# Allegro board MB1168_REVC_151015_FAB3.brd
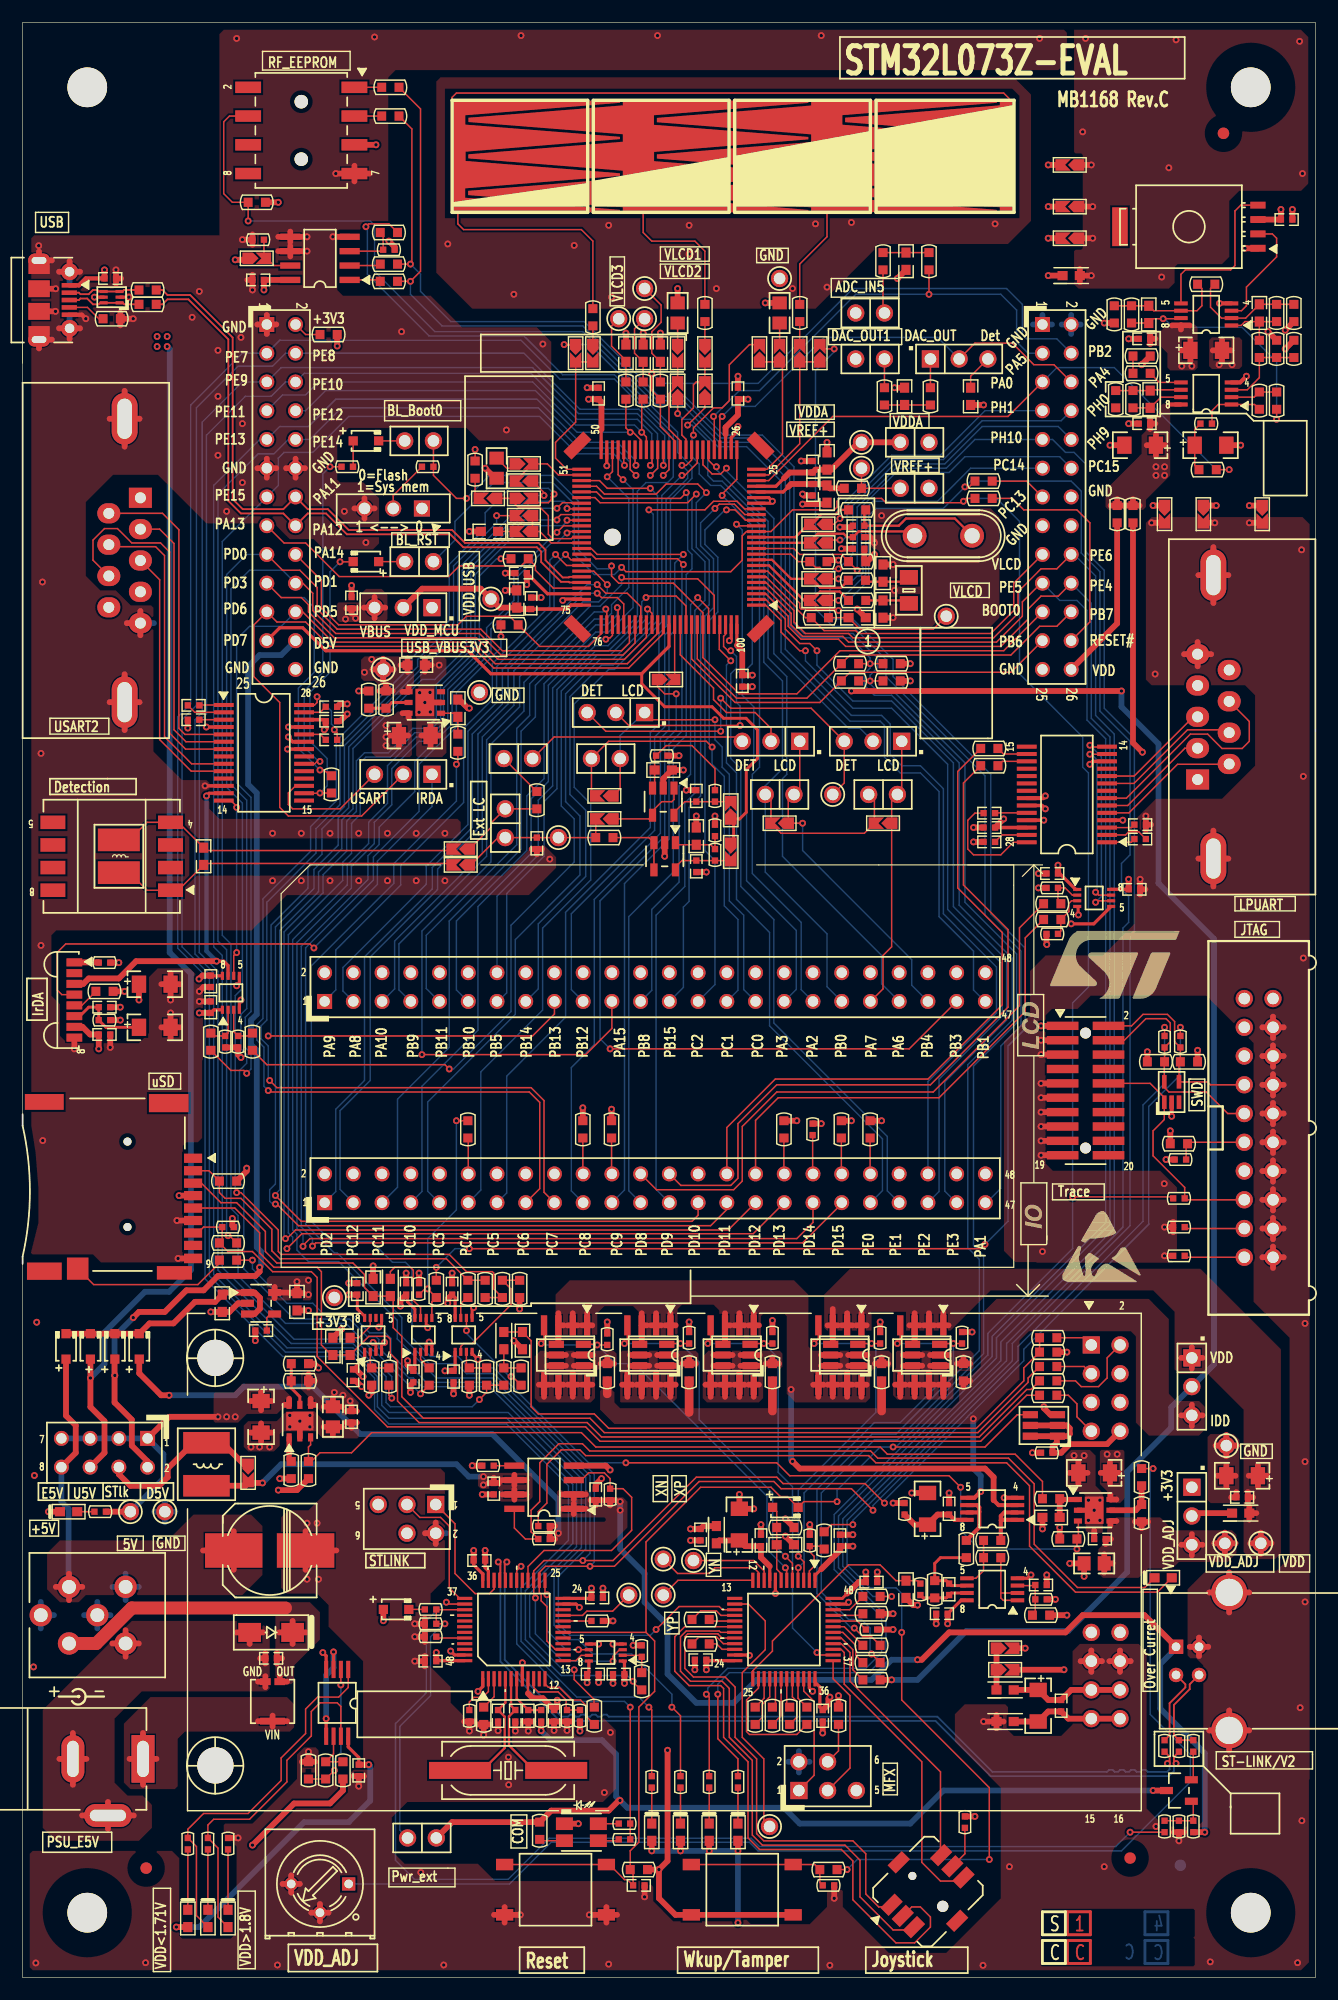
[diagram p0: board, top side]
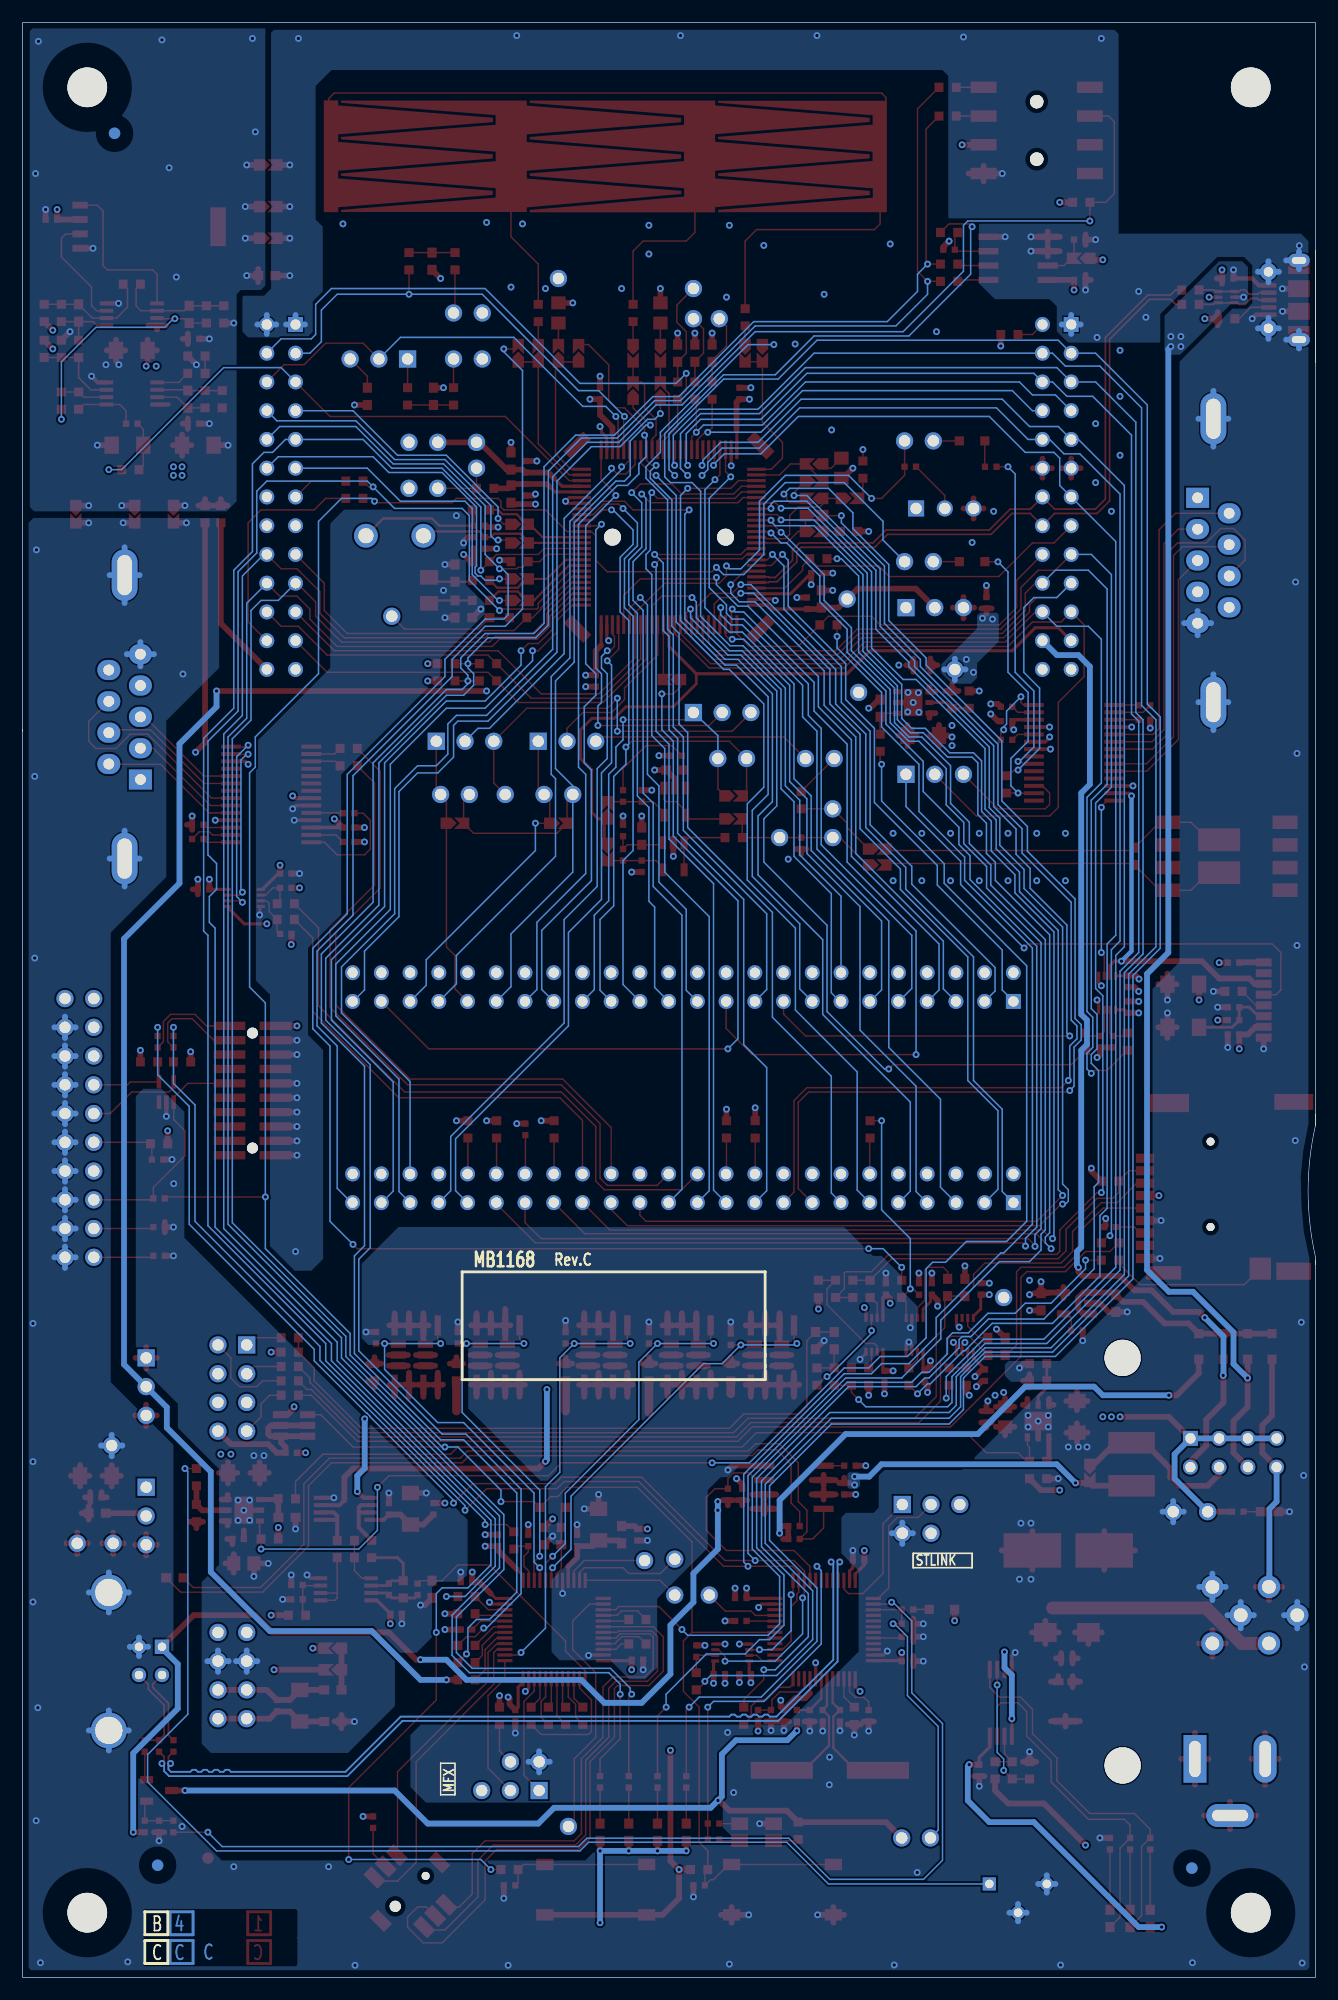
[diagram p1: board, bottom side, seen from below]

Outline 114.3 x 172.72 mm; copper layers: TOP, L2_VCC, L3_GND, BOTTOM. Coordinates in mm from the lower left corner of the outline.
Outline path: 0,76.26 0,76.2 0,172.72 114.3,172.72 114.3,110.11 114.3,110.29 114.3,0 0,0 0,63.37 0,63.01 0,63.69 arc(0.64,69.47) 0,75.25 ; 0,76.26 0,75.25 ; 0,76.26 0,75.25

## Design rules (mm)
net group DIFFPAIR2: nets PA11 PA12
net group DIFFPAIR3: nets STL_USB_DM STL_USB_DP
net group MICROB: nets MICROB_N MICROB_P

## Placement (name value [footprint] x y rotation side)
B1  RESET  [PB10]  47.12 7.75 0 top
B2  WKUP  [PB10]  63.63 7.75 0 top
B3  MT008-A  [MT-008A]  80.01 7.62 315 top
C1  100nF  [0402C]  111.76 155.32 180 top
C2  [N_A]  [0603C]  78.11 151.64 90 top
C3  100nF  [0402C]  20.83 149.99 0 top
C4  47nF  [0805C]  57.91 147.07 270 top
C5  47nF  [0805C]  66.93 147.07 270 top
C6  1uF  [0603C]  109.35 147.07 270 top
C7  1uF  [0603C]  99.57 146.94 270 top
C8  100nF  [0402C]  99.19 144.78 0 top
C9  1uF  [TAN-A]  104.65 143.76 180 top
C10  1uF  [0603C]  53.34 143.51 270 top
C11  1uF  [0603C]  54.86 143.51 270 top
C12  1uF  [0603C]  56.39 143.51 270 top
C13  100nF  [0402C]  50.93 139.95 270 top
C14  100nF  [0402C]  63.25 139.95 270 top
C15  [N_A]  [0603C]  77.98 139.7 270 top
C16  [N_A]  [0603C]  99.69 139.45 90 top
C17  100nF  [0402C]  99.19 137.29 0 top
C18  1uF  [TAN-A]  98.81 135.38 0 top
C19  10uF  [TAN-A]  105.03 135.38 180 top
C20  1uF  [0603C]  71.12 133.99 90 top
C21  100nF  [0402C]  69.85 133.48 270 top
C22  47nF  [0805C]  41.91 133.35 90 top
C23  100nF  [0402C]  69.85 131.44 90 top
C24  1uF  [0603C]  71.12 131.06 270 top
C25  20pF  [0402C]  73.91 128.27 180 top
C26  220nF  [0603C]  41.27 127.76 0 top
C27  20pF  [0402C]  73.91 127.25 0 top
C28  100nF  [0402C]  73.91 126.24 0 top
C29  100nF  [0402C]  44.07 124.08 0 top
C30  2.7pF  [0603C]  76.07 124.08 90 top
C31  1uF  [0603C]  43.69 121.79 90 top
C32  100nF  [0402C]  29.08 121.46 90 top
C33  100nF  [0402C]  44.96 121.41 270 top
C34  2.7pF  [0603C]  76.07 120.9 270 top
C35  1uF  [0603C]  73.79 120.14 180 top
C36  1uF  [0603C]  34.8 115.95 0 top
C37  100nF  [0402C]  63.63 114.55 90 top
C38  100nF  [0402C]  15.11 112.39 180 top
C39  100nF  [0402C]  27.3 112.27 0 top
C40  1nF  [0603C]  16 99.06 90 top
C41  1nF  [0603C]  38.48 112.14 90 top
C42  100nF  [0402C]  15.11 111.12 180 top
C43  100nF  [0402C]  27.3 111 180 top
C44  4.7uF  [TAN-A]  34.67 109.73 180 top
C45  100nF  [0402C]  27.3 109.35 0 top
C46  100pF  [0402C]  45.47 100.2 90 top
C47  [N_A]  [0603C]  56.64 106.68 0 top
C48  100nF  [0402C]  50.67 42.67 90 top
C49  100nF  [0402C]  7.75 150.11 0 top
C50  100nF  [0402C]  85.47 102.87 180 top
C51  100nF  [0402C]  98.81 101.85 0 top
C52  100nF  [0402C]  85.47 101.6 0 top
C53  100nF  [0402C]  98.81 100.58 0 top
C54  100nF  [0402C]  41.66 43.18 90 top
C55  100nF  [0402C]  85.47 100.33 180 top
C56  100nF  [0402C]  91.03 97.54 0 top
C57  [N_A]  [0603C]  59.56 100.84 90 top
C58  100nF  [0402C]  59.56 104.39 90 top
C59  1nF  [0603C]  83.82 139.7 270 top
C60  100nF  [0402C]  98.3 96.14 180 top
C61  N_A  [0603C]  27.43 55.75 270 top
C62  N_A  [0603C]  30.99 60.96 270 top
C63  1nF  [0402C]  59.56 98.17 270 top
C64  100nF  [0402C]  16.64 88.01 90 top
C65  4.7uF  [TAN-A]  11.68 87.76 180 top
C66  100nF  [0402C]  7.24 85.72 180 top
C67  100nF  [0402C]  16.64 85.72 270 top
C68  4.7uF  [TAN-A]  11.68 83.95 180 top
C69  100nF  [0402C]  7.24 83.31 180 top
C70  100nF  [0402C]  29.59 60.83 270 top
C71  100nF  [0402C]  33.91 60.83 270 top
C72  100nF  [0402C]  37.97 60.83 270 top
C73  1uF  [0603C]  24.26 59.69 270 top
C74  1uF  [0603C]  17.65 59.56 270 top
C75  10nF  [0402C]  21.08 57.15 180 top
C76  100nF  [0402C]  29.21 53.21 90 top
C77  100nF  [0402C]  34.54 53.09 90 top
C78  100nF  [0402C]  38.1 53.09 90 top
C79  4.7uF  [TAN-A]  21.08 49.53 90 top
C80  10uF[ESR<0.2ohm]  [0805C]  27.43 49.53 270 top
C81  100nF  [0402C]  29.08 49.53 270 top
C82  4.7uF  [TAN-A]  94.74 44.58 0 top
C83  1uF  [TAN-A]  107.82 44.32 0 top
C84  N_A  [0603C]  44.2 56.26 90 top
C86  100nF  [0402C]  107.82 42.42 0 top
C87  10uF  [TAN-A]  80.01 41.4 270 top
C88  100nF  [0402C]  81.92 41.4 90 top
C89  [N_A]  [0603C]  90.93 40.64 0 top
C90  1uF  [TAN-A]  63.37 40.01 270 top
C91  100nF  [0402C]  59.94 39.12 90 top
C92  100nF  [0402C]  95.25 38.73 180 top
C93  100nF  [0402C]  65.28 38.61 270 top
C94  100nF  [0402C]  72.26 38.61 270 top
C95  [N_A]  [0603C]  67.44 38.23 180 top
C96  220uF  [C310M-6]  21.84 37.72 180 top
C97  100nF  [0402C]  40.39 36.83 180 top
C98  10uF[ESR<0.2ohm]  [0805C]  94.74 36.58 180 top
C99  100nF  [0402C]  75.06 34.92 180 top
C100  100nF  [0402C]  90.04 34.67 0 top
C101  1uF  [0603C]  78.11 34.29 90 top
C102  100nF  [0402C]  81.92 34.29 270 top
C103  100nF  [0402C]  50.8 33.53 180 top
C104  100nF  [0402C]  81.28 32.13 180 top
C105  100nF  [0402C]  21.97 28.19 180 top
C106  100nF  [0402C]  59.94 28.07 0 top
C107  100nF  [0402C]  36.07 27.94 0 top
C108  100nF  [0402C]  50.42 26.8 0 top
C109  100nF  [0402C]  52.7 26.8 180 top
C110  10uF  [TAN-A]  89.79 24 90 top
C111  100nF  [0402C]  91.82 24 270 top
C112  20pF  [0402C]  42.04 23.11 90 top
C113  20pF  [0402C]  43.56 23.11 90 top
C114  100nF  [0402C]  44.7 23.11 90 top
C115  100nF  [0402C]  46.99 23.11 270 top
C116  100nF  [0402C]  70.74 23.11 270 top
C117  100nF  [0402C]  29.72 18.29 90 top
C118  100nF  [0402C]  54.48 8.13 180 top
CN1  -  [SSM-104-L-DH]  24.64 163.19 90 top
CN2  Header 2X1  [SIP2]  73.66 147.07 0 top
CN3  Header 2X1  [SIP2]  73.66 143 0 top
CN4  Header 13X2  [HDR_2X13_2R54]  21.59 146.05 270 top
CN5  Header 13X2  [HDR_2X13_2R54]  90.17 146.05 270 top
CN6  DB9-male  [DB9_M]  10.41 125.2 90 top
CN7  DB9-male  [DB9_M]  103.89 111.38 270 top
CN8  Header 2X1  [SIP2]  42.67 100.71 90 top
CN9  1050170001  [MICRO_USB_B_105017]  4.05 148.21 270 top
CN10  Header 24X2  [HDR_2X24_2R54]  26.7 86.23 0 top
CN11  -  [FTSH-110-01-L-DV]  93.98 78.36 270 top
CN12  JTAG  [IDC20S]  108.01 86.49 0 top
CN13  PJS008-2000 (SMS064FF or SMS128FF)  [MSD_PJS008_]  9.27 73.85 270 top
CN14  Header 24X2  [HDR_2X24_2R54]  26.7 68.45 0 top
CN15  [N_A]  [HDR_2X3-1_2R54-6]  36.52 41.78 180 top
CN16  2.4" LCD connector (MB895_S)  [MB895CS]  94.49 55.88 0 top
CN17  USB-typeB connector  [USB-B]  101.98 29.21 90 top
CN18  DC-10B  [PWR_JACK_DC10]  10.64 19.3 0 top
CN19  [N_A]  [HDR_2X3-1_2R54-6]  68.63 16.51 0 top
D1  BAT60JFILM  [SOD-323]  30.35 135.76 0 top
D2  BAT60JFILM  [SOD-323]  30.35 125.09 180 top
D3  BAT60JFILM  [SOD-323]  3.84 55.75 90 top
D4  BAT60JFILM  [SOD-323]  5.99 55.75 90 top
D5  BAT60JFILM  [SOD-323]  8.15 55.75 90 top
D6  BAT60JFILM  [SOD-323]  10.31 55.75 90 top
D7  BAT60JFILM  [SOD-323]  33.02 32.51 0 top
D8  BAT60JFILM  [SOD-323]  67.44 41.53 0 top
JP1  -  [SIP3]  77.72 109.22 180 top
JP2  -  [SIP3]  80.26 143 0 top
JP3  -  [SIP2]  36.32 135.76 180 top
JP4  -  [SIP2]  80.14 135.64 180 top
JP5  -  [SIP2]  80.14 131.57 180 top
JP6  -  [SIP2]  36.32 125.09 180 top
JP7  -  [SIP3]  36.2 121.03 180 top
JP8  -  [SIP2]  42.55 107.7 0 top
JP9  -  [SIP3]  36.2 106.3 180 top
JP10  -  [SIP3]  103.38 54.74 270 top
JP11  Header 4X2  [HDR_2X4_2R54]  11.05 47.62 180 top
JP12  -  [SIP3]  103.38 43.31 270 top
JP13  -  [SIP2]  36.58 12.32 180 top
JP14  -  [SIP2]  74.8 104.52 0 top
JP15  -  [SIP3]  68.71 109.22 180 top
JP16  -  [SIP2]  65.66 104.52 0 top
JP17  -  [SIP3]  54.99 111.76 180 top
JP18  -  [SIP2]  50.29 107.7 0 top
L1  BEAD  [0603L]  92.71 150.37 0 top
L2  100uH  [ER95]  7.87 99.06 180 top
L3  [N_A)  [LSM2_4R4X3R2_H3]  8.51 99.06 90 top
L4  BEAD  [0603L]  28.96 55.75 270 top
L5  82 10%  [LSM2_4R9X4R9_H4R1]  16.26 45.34 270 top
L6  BEAD  [0603L]  107.7 41.02 0 top
L7  BEAD  [0603L]  61.34 39.12 270 top
L8  BNX002-01  [BNX001]  6.6 32 180 top
L9  BEAD  [0603L]  86.87 25.4 0 top
L10  BEAD  [0603L]  86.87 22.61 0 top
L11  BEAD  [0603L]  32.51 60.96 270 top
L12  BEAD  [0603L]  42.55 56.26 90 top
LD1  Green  [0603D]  63.25 12.83 90 top
LD2  Orange  [0603D]  60.71 12.83 90 top
LD3  Red  [0603D]  58.17 12.83 90 top
LD4  Blue  [0603D]  55.63 12.83 90 top
LD5  Red  [0603D]  4.06 41.15 180 top
LD6  HSMF-A201-A00J1  [LED2_3528]  49.4 12.83 270 top
LD7  Red  [0603D]  14.61 5.21 90 top
LD8  Orange  [0603D]  16.38 5.21 90 top
LD9  Green  [0603D]  18.16 5.21 90 top
LD10  Red  [0603D]  100.84 35.31 180 top
LS1  LS4  [LINEAR_SENSOR3_ELECTRODES]  37.97 155.96 0 top
NOREF  -  []  395.73 -43.74 0 top
NOREF#2  -  [unnamed#2]  5.71 167 0 top
NOREF#3  -  []  93.39 1.48 0 top
NOREF#4  -  []  0 0 0 top
NOREF#5  -  [unnamed#2]  108.58 5.71 0 top
NOREF#6  -  [unnamed#2]  108.58 167 0 top
NOREF#7  -  [unnamed#2]  10.92 9.65 0 top
NOREF#8  -  []  -0.51 -7.11 0 top
NOREF#9  -  []  0 172.72 0 top
NOREF#10  -  [unnamed#2]  106.17 162.94 0 top
NOREF#11  -  []  93.39 4.02 0 top
NOREF#12  -  [unnamed#2]  5.71 5.71 0 top
NOREF#13  -  []  233.48 163.12 0 top
NOREF#14  -  []  170.18 202.69 0 top
NOREF#15  -  [unnamed#2]  97.92 10.54 0 top
NOREF#16  -  []  114.3 0 90 top
NOREF#17  -  []  6.35 209.55 0 top
NOREF#18  -  [unnamed#2]  10.92 9.65 180 bottom
NOREF#19  -  [unnamed#2]  106.17 162.94 180 bottom
NOREF#20  -  [unnamed#2]  102.36 9.91 180 bottom
R1  0  [0603R]  32.51 167 180 top
R2  0  [0603R]  32.51 164.47 180 top
R3  [N_A]  [0603R]  20.7 156.84 0 top
R4  0  [0603R]  32.38 154.18 0 top
R5  10K  [0402R]  20.83 153.54 180 top
R6  10K  [0402R]  32.38 152.65 180 top
R7  0  [0603R]  76.07 151.64 90 top
R8  0  [0603R]  80.14 151.64 270 top
R9  0  [0603R]  32.38 151.38 180 top
R10  0  [0603R]  32.38 149.86 180 top
R11  220 0.1%  [0603R]  104.65 149.61 180 top
R12  10K  [0603R]  60.33 147.07 90 top
R13  10K  [0603R]  68.71 147.07 90 top
R14  47K 0.1%  [0603R]  110.87 147.07 90 top
R15  27400 0.1%  [0603R]  112.39 147.07 90 top
R16  27400 0.1%  [0603R]  96.52 146.94 270 top
R17  47K 0.1%  [0603R]  98.04 146.94 90 top
R18  10K  [0603R]  50.42 146.69 90 top
R19  0  [0603R]  27.05 145.16 180 top
R20  10K 0.1%  [0603R]  109.35 143.89 90 top
R21  20K 0.1%  [0603R]  110.87 143.89 90 top
R22  20K 0.1%  [0603R]  112.39 143.89 90 top
R23  0  [0603R]  98.93 143.26 0 top
R24  0  [0603R]  98.93 141.73 180 top
R25  0  [0603R]  53.34 140.21 90 top
R26  0  [0603R]  54.86 140.21 90 top
R27  0  [0603R]  56.39 140.21 90 top
R28  0  [0603R]  76.2 139.7 270 top
R29  0  [0603R]  80.26 139.7 90 top
R30  [N_A]  [0603R]  96.65 139.45 270 top
R31  0  [0603R]  98.17 139.45 90 top
R32  10K 0.1%  [0603R]  109.35 139.32 90 top
R33  10K 0.1%  [0603R]  110.87 139.32 270 top
R34  100  [0402R]  104.65 137.29 0 top
R35  150  [0402R]  28.7 133.48 180 top
R36  10K  [0402R]  35.81 133.48 180 top
R37  10K  [0603R]  40.01 133.22 270 top
R38  0  [0603R]  104.78 133.22 0 top
R39  820  [0603R]  84.96 132.21 0 top
R40  0  [0603R]  73.41 131.57 180 top
R41  820  [0603R]  84.96 130.68 0 top
R42  390  [0603R]  73.79 129.67 0 top
R43  [N_A]  [0603R]  96.77 129.29 90 top
R44  0  [0603R]  98.17 129.29 90 top
R45  0  [0603R]  43.94 125.35 0 top
R46  [N_A]  [0603R]  70.36 125.09 180 top
R47  [N_A]  [0603R]  73.79 125.09 180 top
R48  0  [0603R]  73.76 123.44 180 top
R49  0  [0603R]  73.79 121.67 180 top
R50  0  [0603R]  70.48 120.14 0 top
R51  0  [0603R]  43.05 119.51 0 top
R52  0  [0603R]  73.15 116.08 0 top
R53  1K2  [0603R]  76.83 116.08 0 top
R54  330K  [0402R]  61.21 104.39 90 top
R55  0  [0603R]  73.15 114.55 0 top
R56  1K2  [0603R]  76.83 114.55 0 top
R57  11.8K[1%]  [0603R]  30.61 112.9 90 top
R58  20.5K[1%]  [0603R]  32.13 112.9 270 top
R59  120  [0603R]  45.47 104.01 90 top
R60  820  [0603R]  38.48 109.09 90 top
R61  0  [0603R]  85.47 108.58 0 top
R62  0  [0603R]  85.47 107.06 0 top
R63  0  [0603R]  27.3 105.41 90 top
R64  330K  [0402R]  56.52 107.95 0 top
R65  1K  [0402R]  46.1 39.88 180 top
R66  2K2  [0402R]  41.15 45.21 180 top
R67  0  [0603R]  51.44 100.71 0 top
R68  100K  [0402R]  46.1 38.73 180 top
R69  0  [0603R]  11.05 149.1 180 top
R70  0  [0603R]  11.05 147.83 180 top
R71  10K  [0402R]  51.94 42.67 270 top
R72  0  [0603R]  90.68 56.52 0 top
R73  330K  [0402R]  61.21 99.19 90 top
R74  100K  [0603R]  7.87 146.56 180 top
R75  0  [0603R]  90.68 52.7 0 top
R76  330K  [0402R]  61.21 101.35 90 top
R83  100K  [0402R]  91.03 96.27 180 top
R87  0  [0603R]  91.03 94.87 0 top
R88  0  [0603R]  91.03 93.47 0 top
R89  100K  [0402R]  91.03 92.2 180 top
R90  5.1  [0402R]  7.24 89.66 180 top
R91  0  [0603R]  7.24 87.12 0 top
R92  47  [0402R]  7.24 84.58 180 top
R93  0  [0603R]  16.64 82.68 270 top
R94  100K  [0402R]  17.91 82.68 270 top
R95  100K  [0402R]  19.05 82.68 270 top
R96  0  [0603R]  20.32 82.68 270 top
R97  22  [0402R]  100.97 82.68 90 top
R98  22  [0402R]  102.36 82.68 90 top
R99  [N_A]  [0603R]  100.2 80.9 0 top
R100  [N_A]  [0603R]  103.12 80.9 0 top
R101  [N_A]  [0603R]  39.37 74.93 270 top
R102  330  [0603R]  49.53 74.93 270 top
R103  330  [0603R]  52.07 74.93 270 top
R104  330  [0603R]  67.31 74.93 270 top
R105  1K  [0402R]  69.85 74.93 90 top
R106  10K  [0603R]  72.39 74.93 270 top
R107  100K  [0603R]  74.93 74.93 270 top
R108  [N_A]  [0603R]  102.23 73.66 180 top
R109  10K  [0402R]  102.36 72.26 0 top
R110  [N_A]  [0603R]  18.16 70.36 0 top
R111  22  [0402R]  102.23 68.83 180 top
R112  10K  [0402R]  18.16 66.29 180 top
R113  10K  [0402R]  102.23 66.29 0 top
R114  0  [0603R]  18.16 64.9 0 top
R115  10K  [0402R]  102.23 63.75 0 top
R116  0  [0603R]  18.16 63.37 180 top
R117  10K  [0402R]  35.05 60.83 90 top
R118  0  [0603R]  36.58 60.83 90 top
R119  0  [0603R]  39.37 60.83 270 top
R120  [N_A]  [0603R]  40.89 60.83 90 top
R121  0  [0603R]  42.42 60.83 270 top
R122  100K  [0603R]  43.94 60.83 270 top
R123  100K  [0402R]  58.93 56.52 90 top
R124  100K  [0402R]  66.29 56.52 90 top
R125  100K  [0402R]  75.82 56.52 90 top
R126  100K  [0402R]  83.06 56.52 90 top
R127  100K  [0402R]  51.69 56.39 90 top
R128  [N_A]  [0603R]  90.68 55.24 0 top
R129  11.8K[1%]  [0603R]  24.51 54.23 0 top
R130  100 [1%]  [0603R]  51.69 53.47 90 top
R131  10 [1%]  [0603R]  58.93 53.47 90 top
R132  1K [1%]  [0603R]  66.29 53.47 90 top
R133  10K [1%]  [0603R]  75.95 53.47 90 top
R134  1 [1%]  [0603R]  83.19 53.47 90 top
R135  270  [0603R]  90.68 53.98 180 top
R136  100K  [0603R]  30.86 53.09 270 top
R137  0  [0603R]  32.38 53.09 270 top
R138  0  [0603R]  35.94 53.09 270 top
R139  100K  [0603R]  39.5 53.09 270 top
R140  0  [0603R]  41.02 53.09 90 top
R141  [N_A]  [0603R]  42.55 53.09 90 top
R142  0  [0603R]  44.07 53.09 270 top
R143  20.5K[1%]  [0603R]  24.51 52.7 180 top
R144  270  [0603R]  90.68 51.44 0 top
R145  4K7  [0402R]  90.55 46.35 180 top
R147  [N_A]  [0603R]  23.75 44.83 270 top
R148  1M  [0603R]  25.27 44.83 90 top
R149  10.2K[1%]  [0603R]  98.93 44.2 90 top
R150  0  [0603R]  90.93 42.29 0 top
R151  100  [0402R]  77.98 41.4 270 top
R153  1K  [0402R]  6.86 41.15 0 top
R154  20K[1%]  [0603R]  98.93 41.02 90 top
R155  [N_A]  [0603R]  67.44 39.75 180 top
R156  1M  [0603R]  92.46 38.73 0 top
R157  100K  [0402R]  69.6 38.61 90 top
R158  0  [0603R]  70.87 38.61 270 top
R159  1K [0.1%]  [0603R]  85.72 38.61 180 top
R162  1K [0.1%]  [0603R]  83.44 37.85 270 top
R163  49K9 [0.1%]  [0603R]  85.72 37.08 0 top
R164  100  [0402R]  79.38 34.29 270 top
R165  49K9 [0.1%]  [0603R]  80.64 34.29 270 top
R166  0  [0603R]  75.06 33.66 180 top
R167  1K  [0402R]  90.04 33.4 0 top
R168  2K2  [0402R]  36.07 32.51 180 top
R169  10K  [0603R]  75.06 32.13 180 top
R170  22K  [0603R]  90.04 32 180 top
R171  10K  [0603R]  59.94 31.62 180 top
R172  100K  [0402R]  50.8 31.5 0 top
R173  4K7  [0402R]  36.07 31.24 0 top
R174  510  [0402R]  75.06 30.73 0 top
R175  100K  [0402R]  36.07 30.1 180 top
R176  [N_A]  [0603R]  59.94 29.46 0 top
R177  0  [0603R]  75.06 29.34 180 top
R178  100K  [0402R]  54.74 28.83 270 top
R179  0  [0603R]  75.06 27.81 180 top
R180  0  [0603R]  75.06 26.29 0 top
R181  0  [0603R]  54.74 26.16 90 top
R182  10K  [0402R]  39.5 23.11 90 top
R183  [N_A]  [0603R]  40.77 23.11 90 top
R184  100K  [0402R]  45.85 23.11 270 top
R185  4K7  [0402R]  48.13 23.11 270 top
R186  4K7  [0402R]  49.28 23.11 90 top
R187  0  [0603R]  50.55 23.11 90 top
R188  10K  [0603R]  64.77 23.11 90 top
R189  10K  [0603R]  66.29 23.11 90 top
R190  10K  [0603R]  67.82 23.11 90 top
R191  10K  [0603R]  69.34 23.11 90 top
R192  0  [0603R]  72.14 23.11 90 top
R193  22  [0402R]  100.97 20.45 90 top
R194  22  [0402R]  102.23 20.45 90 top
R195  1.5K  [0402R]  103.5 20.45 90 top
R196  1.15K [1%]  [0603R]  25.27 18.29 90 top
R197  49.9 [1%]  [0603R]  26.8 18.29 270 top
R198  1K [1%]  [0603R]  28.32 18.29 90 top
R199  680  [0402R]  55.63 17.27 270 top
R200  680  [0402R]  58.17 17.27 270 top
R201  680  [0402R]  60.71 17.27 270 top
R202  510  [0402R]  63.25 17.27 270 top
R203  100  [0402R]  83.31 13.72 270 top
R204  100  [0402R]  53.21 13.59 180 top
R205  100  [0402R]  100.97 13.34 90 top
R206  36K  [0402R]  102.23 13.34 270 top
R207  10K  [0402R]  103.5 13.34 90 top
R208  0  [0603R]  45.72 12.95 90 top
R209  100  [0402R]  53.21 12.19 180 top
R210  1K  [0402R]  14.61 11.81 90 top
R211  1K  [0402R]  16.38 11.81 90 top
R212  1K  [0402R]  18.16 11.81 90 top
R213  [N_A]  [0603R]  54.48 9.53 0 top
R214  330  [0603R]  71.25 9.53 0 top
R215  220K  [0402R]  71.25 8.13 0 top
RV1  3386P-503H[5%]  [3386P]  26.29 8.26 180 top
SB1  Closed by default  [SB_0603]  92.58 160.15 0 top
SB2  Closed by default  [SB_0603]  92.58 156.46 0 top
SB3  Closed by default  [SB_0603]  92.58 153.67 0 top
SB4  Closed by default  [SB_0603]  20.7 151.89 180 top
SB5  Closed by default  [SB_0603]  48.9 143.51 90 top
SB6  Open by default  [SB_0603]  50.42 143.51 90 top
SB7  Open by default  [SB_0603]  57.91 143.51 90 top
SB8  Open by default  [SB_0603]  60.33 143.51 90 top
SB9  Closed by default  [SB_0603]  65.15 143.51 270 top
SB10  Open by default  [SB_0603]  66.93 143.51 270 top
SB11  Open by default  [SB_0603]  68.7 143.51 270 top
SB12  Closed by default  [SB_0603]  70.48 143.51 270 top
SB13  Closed by default  [SB_0603]  57.91 140.21 270 top
SB14  Closed by default  [SB_0603]  60.33 140.21 270 top
SB15  Open by default  [SB_0603]  44.32 133.73 180 top
SB16  Closed by default  [SB_0603]  44.32 132.21 0 top
SB17  Open by default  [SB_0603]  41.15 130.68 0 top
SB18  Closed by default  [SB_0603]  44.32 130.68 180 top
SB19  Closed by default  [SB_0603]  100.97 129.29 90 top
SB20  Closed by default  [SB_0603]  104.39 129.29 90 top
SB21  Closed by default  [SB_0603]  109.6 129.28 90 top
SB22  Closed by default  [SB_0603]  44.32 129.16 0 top
SB23  Open by default  [SB_0603]  70.36 128.39 0 top
SB24  Open by default  [SB_0603]  44.32 127.76 0 top
SB25  Open by default  [SB_0603]  70.36 126.74 0 top
SB26  Open by default  [SB_0603]  70.36 123.57 0 top
SB27  Open by default  [SB_0603]  70.36 121.67 0 top
SB28  Open by default  [SB_0603]  76.07 101.98 0 top
SB29  Closed by default  [SB_0603]  38.73 99.69 0 top
SB30  Closed by default  [SB_0603]  38.73 98.3 0 top
SB31  Closed by default  [SB_0603]  62.61 99.44 90 top
SB32  Open by default  [SB_0603]  62.61 103.12 270 top
SB33  Open by default  [SB_0603]  51.44 102.36 0 top
SB34  Open by default  [SB_0603]  66.93 101.98 0 top
SB35  Closed by default  [SB_0603]  56.9 114.68 180 top
SB36  Open by default  [SB_0603]  51.44 104.39 0 top
SB38  Open by default  [SB_0603]  19.94 44.58 90 top
SB40  Closed by default  [SB_0603]  86.87 29.09 180 top
SB41  Open by default  [SB_0603]  86.87 27.18 180 top
SW1  09.03290.01  [SW1_3TH_2R54_10X2R5]  35.31 129.79 180 top
T1  STS9P2UH7  [SOIC8_1R27_4R9X6]  48.01 54.99 180 top
T2  STT7P2UH7  [SOT23-6L]  48.39 54.99 90 top
T3  STS9P2UH7  [SOIC8_1R27_4R9X6]  55.37 54.99 180 top
T4  STT7P2UH7  [SOT23-6L]  55.75 54.99 90 top
T5  STS9P2UH7  [SOIC8_1R27_4R9X6]  62.74 54.99 180 top
T6  STT7P2UH7  [SOT23-6L]  63.12 54.99 90 top
T7  STS9P2UH7  [SOIC8_1R27_4R9X6]  72.26 54.99 180 top
T8  STT7P2UH7  [SOT23-6L]  72.64 54.99 90 top
T9  STS9P2UH7  [SOIC8_1R27_4R9X6]  79.5 54.99 180 top
T10  STT7P2UH7  [SOT23-6L]  79.88 54.99 90 top
T11  STT5N2VH5  [SOT23-6L]  90.3 48.77 90 top
T14  9013-SOT23  [SOT-23]  102.23 16.51 90 top
TP1  -  [TP]  66.93 150.11 0 top
TP2  -  [TP]  54.99 149.22 180 top
TP3  -  [TP]  52.7 146.56 270 top
TP4  -  [TP]  54.99 146.56 270 top
TP5  -  [TP]  74.17 135.64 0 top
TP6  -  [TP]  74.17 133.35 0 top
TP7  -  [TP]  41.4 121.79 0 top
TP8  -  [TP]  81.66 120.27 0 top
TP9  -  [TP]  31.88 115.57 90 top
TP10  -  [TP]  40.39 113.54 270 top
TP14  -  [TP]  47.37 100.71 90 top
TP18  -  [TP]  71.63 104.52 0 top
TP20  -  [TP]  27.56 60.07 0 top
TP21  -  [TP]  106.43 46.99 0 top
TP22  -  [TP]  9.53 41.15 180 top
TP23  -  [TP]  12.57 41.15 180 top
TP24  -  [TP]  106.3 38.35 90 top
TP25  -  [TP]  109.47 38.35 180 top
TP26  [N_A]  [TP]  56.64 36.96 90 top
TP27  [N_A]  [TP]  59.31 36.83 90 top
TP28  [N_A]  [TP]  53.59 33.78 0 top
TP29  [N_A]  [TP]  56.64 33.78 90 top
TP31  [N_A]  [TP]  66.04 13.34 0 top
U1  MPXM2102AS  [SENSOR_MPXM2102AS]  103.12 154.69 90 top
U2  STLM75M2F  [SOIC8_1R27_4R9X6]  26.29 151.89 90 top
U3  TSZ122IST  [MSOP8_0R65_3X4R9]  104.65 146.94 90 top
U4  TSZ122IST  [MSOP8_0R65_3X4R9]  104.65 139.95 90 top
U5  STM32L073VZT6  [IC149_100_025_B5]  57.15 127.25 90 top
U6  ST1L05BPUR  [DFN6_0R95_3X3]  35.56 112.65 90 top
U7  ST3241EBPR  [SSOP28_0R65_10R2X7R8]  21.34 108.2 270 top
U8  ST3241EBPR  [SSOP28_0R65_10R2X7R8]  92.33 104.52 90 top
U9  TSV631ILT  [SOT-23-5L]  56.77 99.06 180 top
U10  USBLC6-2P6 (optional)  [SOT-563]  7.87 148.46 90 top
U11  TSV911ILT  [SOT-23-5L]  56.64 103.89 180 top
U12  SN74LVC2T45DCUT  [USOP8_0R5_2X3R1]  94.74 95.38 270 top
U13  SN74LVC2T45DCUT  [USOP8_0R5_2X3R1]  18.41 87 0 top
U14  TFDU6300  [IR_VISHAY3]  4.57 86.36 90 top
U15  ESDALC6V1W5  [SOT-353]  101.59 78.23 0 top
U16  LD3985M33R  [SOT23-5]  21.08 59.56 270 top
U17  SN74LVC2T45DCUT  [USOP8_0R5_2X3R1]  30.99 56.77 0 top
U18  SN74LVC2T45DCUT  [USOP8_0R5_2X3R1]  35.43 56.77 0 top
U19  SN74LVC2T45DCUT  [USOP8_0R5_2X3R1]  38.99 56.77 0 top
U20  ST1L05BPUR  [DFN6_0R95_3X3]  24.51 49.15 0 top
U21  TSZ122IST  [MSOP8_0R65_3X4R9]  85.72 41.4 90 top
U22  ST1L05BPUR  [DFN6_0R95_3X3]  94.74 41.27 270 top
U23  TSZ122IST  [MSOP8_0R65_3X4R9]  85.72 34.29 90 top
U24  STLINK  [LQFP48_0R5_9X9]  43.43 30.73 90 top
U25  STM32L152CCT6  [LQFP48_0R5_9X9]  67.31 30.73 270 top
U26  SN74LVC2T45DCUT  [USOP8_0R5_2X3R1]  51.56 28.7 90 top
U27  ZEN056V130A24LS  [TYCO_ZEN056V130A24LS]  22.1 24.38 90 top
U28  TS3702IPT  [TSSOP8_0R65_3X6R4]  27.81 24.26 180 top
U29  ST890CDR  [SOIC8_1R27_4R9X6]  46.1 43.31 90 top
X1  8MHz (with socket)  [XTAL_SOCKET]  83.95 127.38 0 top
X2  NDK NX3215SA-32.768KHZ-EXS00A-MU00525  [XTAL_2SM_3R2X1R5]  78.36 122.56 270 top
X3  8MHz  [XTAL_2SM_12R7X4R7]  42.93 18.29 180 top
Z1  SMAJ5.0A-TR  [SMA]  21.97 30.48 0 top

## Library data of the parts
B1 B2 = PB10
B3 = MT-008A
C1 C3 C8 C13 C14 C17 C21 C23 C25 C27-C29 C32 C33 C37-C39 C42 C43 C45 C46 C48-C56 C58 C60 C63 C64 C66 C67 C69-C72 C75-C78 C81 C86 C88 C91-C94 C97 C99 C100 C102-C109 C111-C118 = 0402C
C2 C6 C7 C10-C12 C15 C16 C20 C24 C26 C30 C31 C34-C36 C40 C41 C47 C57 C59 C61 C62 C73 C74 C84 C89 C95 C101 = 0603C
C4 C5 C22 C80 C98 = 0805C
C9 C18 C19 C44 C65 C68 C79 C82 C83 C87 C90 C110 = TAN-A
C96 = C310M-6
CN1 = SSM-104-L-DH
CN2 CN3 CN8 JP3-JP6 JP8 JP13 JP14 JP16 JP18 = SIP2
CN4 CN5 = HDR_2X13_2R54
CN6 CN7 = DB9_M
CN9 = MICRO_USB_B_105017
CN10 CN14 = HDR_2X24_2R54
CN11 = FTSH-110-01-L-DV
CN12 = IDC20S
CN13 = MSD_PJS008_
CN15 CN19 = HDR_2X3-1_2R54-6
CN16 = MB895CS
CN17 = USB-B
CN18 = PWR_JACK_DC10
D1-D8 = SOD-323
JP1 JP2 JP7 JP9 JP10 JP12 JP15 JP17 = SIP3
JP11 = HDR_2X4_2R54
L1 L4 L6 L7 L9-L12 = 0603L
L2 = ER95
L3 = LSM2_4R4X3R2_H3
L5 = LSM2_4R9X4R9_H4R1
L8 = BNX001
LD1-LD5 LD7-LD10 = 0603D
LD6 = LED2_3528
LS1 = LINEAR_SENSOR3_ELECTRODES
R1-R4 R7-R33 R37-R53 R55-R63 R67 R69 R70 R72 R74 R75 R87 R88 R91 R93 R96 R99-R104 R106-R108 R110 R114 R116 R118-R122 R128-R144 R147-R150 R154-R156 R158 R159 R162 R163 R165 R166 R169-R171 R176 R177 R179-R181 R183 R187-R192 R196-R198 R208 R213 R214 = 0603R
R5 R6 R34-R36 R54 R64-R66 R68 R71 R73 R76 R83 R89 R90 R92 R94 R95 R97 R98 R105 R109 R111-R113 R115 R117 R123-R127 R145 R151 R153 R157 R164 R167 R168 R172-R175 R178 R182 R184-R186 R193-R195 R199-R207 R209-R212 R215 = 0402R
RV1 = 3386P
SB1-SB36 SB38 SB40 SB41 = SB_0603
SW1 = SW1_3TH_2R54_10X2R5
T1 T3 T5 T7 T9 U2 U29 = SOIC8_1R27_4R9X6
T2 T4 T6 T8 T10 T11 = SOT23-6L
T14 = SOT-23
TP1-TP10 TP14 TP18 TP20-TP29 TP31 = TP
U1 = SENSOR_MPXM2102AS
U3 U4 U21 U23 = MSOP8_0R65_3X4R9
U5 = IC149_100_025_B5
U6 U20 U22 = DFN6_0R95_3X3
U7 U8 = SSOP28_0R65_10R2X7R8
U9 U11 = SOT-23-5L
U10 = SOT-563
U12 U13 U17-U19 U26 = USOP8_0R5_2X3R1
U14 = IR_VISHAY3
U15 = SOT-353
U16 = SOT23-5
U24 U25 = LQFP48_0R5_9X9
U27 = TYCO_ZEN056V130A24LS
U28 = TSSOP8_0R65_3X6R4
X1 = XTAL_SOCKET
X2 = XTAL_2SM_3R2X1R5
X3 = XTAL_2SM_12R7X4R7
Z1 = SMA

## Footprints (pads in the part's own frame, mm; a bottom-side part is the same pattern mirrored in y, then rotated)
0402C
  rect 0.559x0.559 smd: 1(-0.508,0) 2(0.508,0)
0402R
  rect 0.559x0.559 smd: 1(-0.508,0) 2(0.508,0)
0603C
  rect 0.889x0.813 smd: 1(-0.762,0) 2(0.762,0)
0603D
  rect 0.889x0.813 smd: 1(-0.762,0) 2(0.762,0)
0603L
  rect 0.889x0.813 smd: 1(-0.762,0) 2(0.762,0)
0603R
  rect 0.787x0.813 smd: 1(-0.762,0) 2(0.762,0)
0805C
  rect 1.143x1.27 smd: 1(-0.889,0) 2(0.889,0)
3386P
  rect 1.168x1.168 hole 0.762: 1(-2.54,0)
  round 1.168 hole 0.762: 2(0,2.54) 3(2.54,0)
BNX001
  round 1.981 hole 1.219: 1(2.5,2.5) 2(-2.5,2.5) 3(2.5,-2.5) 4(0,0) 5(5,0) 6(-2.5,-2.5)
C310M-6
  rect 5.08x3.048 smd: 1(3.175,0) 2(-3.175,0)
DB9_M
  rect 1.778x2.032 hole 0.965: 1(5.537,0)
  oval 1.778x2.032 hole 0.965: 2(2.769,0) 3(0,0) 4(-2.769,0) 5(-5.537,0) 6(4.166,2.794) 7(1.397,2.794) 8(-1.372,2.794) 9(-4.14,2.794)
  oval 4.572x2.286 hole 3.556x1.27: 10(-12.522,1.397) 11(12.522,1.397)
DFN6_0R95_3X3
  rect 0.457x0.711 smd: 1(-0.95,-1.436) 2(0,-1.436) 3(0.95,-1.436) 4(0.95,1.436) 5(0,1.436) 6(-0.95,1.436)
  rect 2.413x1.651 smd: 7(0,0)
ER95
  rect 2.21x1.194 smd: 1(-5.2,3) 2(-5.2,1) 3(-5.2,-1) 4(-5.2,-3) 5(5.2,-3) 6(5.2,-1) 7(5.2,1) 8(5.2,3)
FTSH-110-01-L-DV
  round 0.965 hole 0.965 unplated: (-5.08,0) (5.08,0)
  rect 0.737x2.794 smd: 1(-5.715,-2.03) 2(-5.715,2.03) 3(-4.445,-2.03) 4(-4.445,2.03) 5(-3.175,-2.03) 6(-3.175,2.03) 7(-1.905,-2.03) 8(-1.905,2.03) 9(-0.635,-2.03) 10(-0.635,2.03) 11(0.635,-2.03) 12(0.635,2.03) 13(1.905,-2.03) 14(1.905,2.03) 15(3.175,-2.03) 16(3.175,2.03) 17(4.445,-2.03) 18(4.445,2.03) 19(5.715,-2.03) 20(5.715,2.03)
HDR_2X3-1_2R54-6
  rect 1.524x1.524 hole 1.016: 1(0,0)
  round 1.524 hole 1.016: 2(0,2.54) 3(2.54,0) 4(2.54,2.54) 5(5.08,0)
HDR_2X4_2R54
  rect 1.321x1.321 hole 0.914: 1(0,0)
  round 1.321 hole 0.914: 2(0,2.54) 3(2.54,0) 4(2.54,2.54) 5(5.08,0) 6(5.08,2.54) 7(7.62,0) 8(7.62,2.54)
HDR_2X13_2R54
  rect 1.321x1.321 hole 0.914: 1(0,0)
  round 1.321 hole 0.914: 2(0,2.54) 3(2.54,0) 4(2.54,2.54) 5(5.08,0) 6(5.08,2.54) 7(7.62,0) 8(7.62,2.54) 9(10.16,0) 10(10.16,2.54) 11(12.7,0) 12(12.7,2.54) 13(15.24,0) 14(15.24,2.54) 15(17.78,0) 16(17.78,2.54) 17(20.32,0) 18(20.32,2.54) 19(22.86,0) 20(22.86,2.54) 21(25.4,0) 22(25.4,2.54) 23(27.94,0) 24(27.94,2.54) 25(30.48,0) 26(30.48,2.54)
HDR_2X24_2R54
  rect 1.321x1.321 hole 0.914: 1(0,0)
  round 1.321 hole 0.914: 2(0,2.54) 3(2.54,0) 4(2.54,2.54) 5(5.08,0) 6(5.08,2.54) 7(7.62,0) 8(7.62,2.54) 9(10.16,0) 10(10.16,2.54) 11(12.7,0) 12(12.7,2.54) 13(15.24,0) 14(15.24,2.54) 15(17.78,0) 16(17.78,2.54) 17(20.32,0) 18(20.32,2.54) 19(22.86,0) 20(22.86,2.54) 21(25.4,0) 22(25.4,2.54) 23(27.94,0) 24(27.94,2.54) 25(30.48,0) 26(30.48,2.54) 27(33.02,0) 28(33.02,2.54) 29(35.56,0) 30(35.56,2.54) 31(38.1,0) 32(38.1,2.54) 33(40.64,0) 34(40.64,2.54) 35(43.18,0) 36(43.18,2.54) 37(45.72,0) 38(45.72,2.54) 39(48.26,0) 40(48.26,2.54) 41(50.8,0) 42(50.8,2.54) 43(53.34,0) 44(53.34,2.54) 45(55.88,0) 46(55.88,2.54) 47(58.42,0) 48(58.42,2.54)
IC149_100_025_B5
  round 1.499 hole 1.499 unplated: (0,5) (0,-5)
  rect 1.016x2.489 smd rot 45: 0/3(-8.1,-8.1) 0/4(8.1,8.1)
  rect 1.016x2.489 smd rot 135: 0/5(-8.1,8.1) 0/6(8.1,-8.1)
  rect 0.279x1.651 smd: 1(-6,-7.725) 2(-5.5,-7.725) 3(-5,-7.725) 4(-4.5,-7.725) 5(-4,-7.725) 6(-3.5,-7.725) 7(-3,-7.725) 8(-2.5,-7.725) 9(-2,-7.725) 10(-1.5,-7.725) 11(-1,-7.725) 12(-0.5,-7.725) 13(0,-7.725) 14(0.5,-7.725) 15(1,-7.725) 16(1.5,-7.725) 17(2,-7.725) 18(2.5,-7.725) 19(3,-7.725) 20(3.5,-7.725) 21(4,-7.725) 22(4.5,-7.725) 23(5,-7.725) 24(5.5,-7.725) 25(6,-7.725) 51(6,7.725) 52(5.5,7.725) 53(5,7.725) 54(4.5,7.725) 55(4,7.725) 56(3.5,7.725) 57(3,7.725) 58(2.5,7.725) 59(2,7.725) 60(1.5,7.725) 61(1,7.725) 62(0.5,7.725) 63(0,7.725) 64(-0.5,7.725) 65(-1,7.725) 66(-1.5,7.725) 67(-2,7.725) 68(-2.5,7.725) 69(-3,7.725) 70(-3.5,7.725) 71(-4,7.725) 72(-4.5,7.725) 73(-5,7.725) 74(-5.5,7.725) 75(-6,7.725)
  rect 1.651x0.279 smd: 26(7.725,-6) 27(7.725,-5.5) 28(7.725,-5) 29(7.725,-4.5) 30(7.725,-4) 31(7.725,-3.5) 32(7.725,-3) 33(7.725,-2.5) 34(7.725,-2) 35(7.725,-1.5) 36(7.725,-1) 37(7.725,-0.5) 38(7.725,0) 39(7.725,0.5) 40(7.725,1) 41(7.725,1.5) 42(7.725,2) 43(7.725,2.5) 44(7.725,3) 45(7.725,3.5) 46(7.725,4) 47(7.725,4.5) 48(7.725,5) 49(7.725,5.5) 50(7.725,6) 76(-7.725,6) 77(-7.725,5.5) 78(-7.725,5) 79(-7.725,4.5) 80(-7.725,4) 81(-7.725,3.5) 82(-7.725,3) 83(-7.725,2.5) 84(-7.725,2) 85(-7.725,1.5) 86(-7.725,1) 87(-7.725,0.5) 88(-7.725,0) 89(-7.725,-0.5) 90(-7.725,-1) 91(-7.725,-1.5) 92(-7.725,-2) 93(-7.725,-2.5) 94(-7.725,-3) 95(-7.725,-3.5) 96(-7.725,-4) 97(-7.725,-4.5) 98(-7.725,-5) 99(-7.725,-5.5) 100(-7.725,-6)
IDC20S
  round 1.524 hole 1.016: 1(0,0) 2(2.54,0) 3(0,-2.54) 4(2.54,-2.54) 5(0,-5.08) 6(2.54,-5.08) 7(0,-7.62) 8(2.54,-7.62) 9(0,-10.16) 10(2.54,-10.16) 11(0,-12.7) 12(2.54,-12.7) 13(0,-15.24) 14(2.54,-15.24) 15(0,-17.78) 16(2.54,-17.78) 17(0,-20.32) 18(2.54,-20.32) 19(0,-22.86) 20(2.54,-22.86)
IR_VISHAY3
  rect 0.711x1.397 smd: 1(3.325,0) 2(2.375,0) 3(1.425,0) 4(0.475,0) 5(-0.475,0) 6(-1.425,0) 7(-2.375,0) 8(-3.325,0)
LED2_3528
  rect 1.118x1.499 smd: 1(-0.75,-1.5) 2(-0.75,1.5) 3(0.75,1.5) 4(0.75,-1.5)
LINEAR_SENSOR3_ELECTRODES
  round 0.152 smd: 1(1.016,4.572) 2(16.891,4.572) 3(33.274,4.572) 4(48.514,4.699)
LQFP48_0R5_9X9
  rect 1.346x0.279 smd: 1(-4.35,2.75) 2(-4.35,2.25) 3(-4.35,1.75) 4(-4.35,1.25) 5(-4.35,0.75) 6(-4.35,0.25) 7(-4.35,-0.25) 8(-4.35,-0.75) 9(-4.35,-1.25) 10(-4.35,-1.75) 11(-4.35,-2.25) 12(-4.35,-2.75) 25(4.35,-2.75) 26(4.35,-2.25) 27(4.35,-1.75) 28(4.35,-1.25) 29(4.35,-0.75) 30(4.35,-0.25) 31(4.35,0.25) 32(4.35,0.75) 33(4.35,1.25) 34(4.35,1.75) 35(4.35,2.25) 36(4.35,2.75)
  rect 0.279x1.346 smd: 13(-2.75,-4.35) 14(-2.25,-4.35) 15(-1.75,-4.35) 16(-1.25,-4.35) 17(-0.75,-4.35) 18(-0.25,-4.35) 19(0.25,-4.35) 20(0.75,-4.35) 21(1.25,-4.35) 22(1.75,-4.35) 23(2.25,-4.35) 24(2.75,-4.35) 37(2.75,4.35) 38(2.25,4.35) 39(1.75,4.35) 40(1.25,4.35) 41(0.75,4.35) 42(0.25,4.35) 43(-0.25,4.35) 44(-0.75,4.35) 45(-1.25,4.35) 46(-1.75,4.35) 47(-2.25,4.35) 48(-2.75,4.35)
LSM2_4R4X3R2_H3
  rect 2.007x3.708 smd: 1(-1.45,0) 2(1.45,0)
LSM2_4R9X4R9_H4R1
  rect 1.905x4.115 smd: 1(-1.9,0) 2(1.9,0)
MB895CS
  round 3.2 hole 3.2 unplated: (-77.443,-1.143) (-77.443,-37.153)
  rect 1.524x1.524 hole 1.016: 1(0,0)
  round 1.524 hole 1.016: 2(2.54,0) 3(0,-2.54) 4(2.54,-2.54) 5(0,-5.08) 6(2.54,-5.08) 7(0,-7.62) 8(2.54,-7.62) 9(0,-25.4) 10(2.54,-25.4) 11(0,-27.94) 12(2.54,-27.94) 13(0,-30.48) 14(2.54,-30.48) 15(0,-33.02) 16(2.54,-33.02)
MICRO_USB_B_105017
  rect 0.406x1.346 smd: 1(-1.3,0.075) 2(-0.65,0.075) 3(0,0.075) 4(0.65,0.075) 5(1.3,0.075)
  oval 1.194x1.905 hole 0.61x1.295: 6(-3.5,-2.6) 7(3.5,-2.6)
  round 1.499 hole 0.838: 8(-2.5,0.1) 9(2.5,0.1)
  rect 1.499x1.905 smd: 10(-1,-2.6) 11(1,-2.6)
MSD_PJS008_
  round 0.711 hole 0.711 unplated: (0,0) (7.55,0)
  rect 0.813x1.6 smd: 1(1.475,5.8) 2(2.575,5.8) 3(3.675,5.8) 4(4.775,5.8) 5(5.875,5.8) 6(6.975,5.8) 7(8.075,5.8) 8(9.175,5.8)
  rect 0.838x1.6 smd: 9(10.325,5.8)
  rect 1.956x1.905 smd: 10(11.225,-4.4)
  rect 1.524x3.073 smd: 11(11.45,-7.35)
  rect 1.397x3.429 smd: 12(-3.503,-7.357)
  rect 1.6x3.505 smd: 13(-3.4,3.65)
  rect 1.194x3.099 smd: 14(11.6,4.15)
MSOP8_0R65_3X4R9
  rect 0.356x1.194 smd: 1(-0.975,-2.235) 2(-0.325,-2.235) 3(0.325,-2.235) 4(0.975,-2.235) 5(0.975,2.235) 6(0.325,2.235) 7(-0.325,2.235) 8(-0.975,2.235)
MT-008A
  round 0.711 hole 0.711 unplated: (-1.9,0)
  round 0.991 hole 0.991 unplated: (1.9,0)
  rect 1.016x1.778 smd: 1(-1.4,-3.1) 2(0,-3.1) 3(1.4,-3.1) 4(1.4,3.1) 5(0,3.1) 6(-1.4,3.1) 7(-3.6,0) 8(3.7,0)
PB10
  rect 1.524x1.016 smd: 1(-4.5,-2.223) 2(-4.5,2.223) 3(4.5,2.223) 4(4.5,-2.223)
PWR_JACK_DC10
  rect 2.032x4.216 hole 1.016x3.2: 1(0,0)
  oval 4.216x2.032 hole 3.2x1.016: 2(-3.1,-5)
  oval 2.032x4.216 hole 1.016x3.2: 3(-6.2,0)
SB_0603
  round 0.152 smd: 1(-0.762,0) 2(0.762,0)
SENSOR_MPXM2102AS
  rect 0.61x1.346 smd: 1(-1.905,-6.1) 2(-0.635,-6.1) 3(0.635,-6.1) 4(1.905,-6.1)
  rect 3.429x1.372 smd: 5(0,6.1)
SIP2
  round 1.524 hole 1.016: 1(0,0) 2(2.54,0)
SIP3
  rect 1.524x1.524 hole 1.016: 1(0,0)
  round 1.524 hole 1.016: 2(2.54,0) 3(5.08,0)
SMA
  rect 2.007x1.676 smd: 1(-1.9,0) 2(1.9,0)
SOD-323
  rect 0.813x0.813 smd: 1(-1.125,0) 2(1.125,0)
SOIC8_1R27_4R9X6
  rect 0.559x1.778 smd: 1(-1.905,-2.624) 2(-0.635,-2.624) 3(0.635,-2.624) 4(1.905,-2.624) 5(1.905,2.624) 6(0.635,2.624) 7(-0.635,2.624) 8(-1.905,2.624)
SOT23-5
  rect 0.635x1.143 smd: 1(-0.95,-1.2) 2(0,-1.2) 3(0.95,-1.2) 4(0.95,1.2) 5(-0.95,1.2)
SOT23-6L
  rect 0.635x1.346 smd: 1(-0.95,-1.2) 2(0,-1.2) 3(0.95,-1.2) 4(0.95,1.2) 5(0,1.2) 6(-0.95,1.2)
SOT-23
  rect 0.635x1.143 smd: 1(-0.95,-1.1) 2(0.95,-1.1) 3(0,1.1)
SOT-23-5L
  rect 0.635x1.143 smd: 1(-0.95,-1.2) 2(0,-1.2) 3(0.95,-1.2) 4(0.95,1.2) 5(-0.95,1.2)
SOT-353
  rect 0.406x1.194 smd: 1(-0.65,-0.9) 2(0,-0.9) 3(0.65,-0.9) 4(0.65,0.9) 5(-0.65,0.9)
SOT-563
  rect 0.279x0.711 smd: 1(-0.5,-0.7) 2(0,-0.7) 3(0.5,-0.7) 4(0.5,0.703) 5(0,0.703) 6(-0.5,0.703)
SSM-104-L-DH
  round 1.194 hole 1.194 unplated: (-2.54,0) (2.54,0)
  rect 1.016x2.286 smd: 1(3.81,-4.698) 2(3.81,4.698) 3(1.27,-4.698) 4(1.27,4.698) 5(-1.27,-4.698) 6(-1.27,4.698) 7(-3.81,-4.698) 8(-3.81,4.698)
SSOP28_0R65_10R2X7R8
  rect 0.356x1.753 smd: 1(-4.225,-3.55) 2(-3.575,-3.55) 3(-2.925,-3.55) 4(-2.275,-3.55) 5(-1.625,-3.55) 6(-0.975,-3.55) 7(-0.325,-3.55) 8(0.325,-3.55) 9(0.975,-3.55) 10(1.625,-3.55) 11(2.275,-3.55) 12(2.925,-3.55) 13(3.575,-3.55) 14(4.225,-3.55) 15(4.225,3.55) 16(3.575,3.55) 17(2.925,3.55) 18(2.275,3.55) 19(1.625,3.55) 20(0.975,3.55) 21(0.325,3.55) 22(-0.325,3.55) 23(-0.975,3.55) 24(-1.625,3.55) 25(-2.275,3.55) 26(-2.925,3.55) 27(-3.575,3.55) 28(-4.225,3.55)
SW1_3TH_2R54_10X2R5
  rect 1.422x1.422 hole 1.016: 1(0,0)
  round 1.422 hole 1.016: 2(2.54,0) 3(5.08,0)
TAN-A
  rect 1.27x1.524 smd: 1(1.397,0) 2(-1.397,0)
TP
  round 1.524 hole 1.016: 1(0,0)
TSSOP8_0R65_3X6R4
  rect 0.356x1.524 smd: 1(-0.975,-2.95) 2(-0.325,-2.95) 3(0.325,-2.95) 4(0.975,-2.95) 5(0.975,2.95) 6(0.325,2.95) 7(-0.325,2.95) 8(-0.975,2.95)
TYCO_ZEN056V130A24LS
  rect 0.61x2.21 smd: 1(-1.745,0)
  rect 0.61x0.94 smd: 2(1.745,0.635) 3(1.745,-0.635)
unnamed#2
  round 3.505 hole 3.505 unplated: (0,0)
USB-B
  rect 1.27x1.27 hole 0.762: 1(0,0)
  round 1.27 hole 0.762: 2(-2.489,0) 3(-2.489,-2.032) 4(0,-2.032)
  round 3.175 hole 2.413: 5(-7.391,-4.699) 6(4.801,-4.699)
USOP8_0R5_2X3R1
  rect 0.279x0.711 smd: 1(-0.75,-1.5) 2(-0.25,-1.5) 3(0.25,-1.5) 4(0.75,-1.5) 5(0.75,1.5) 6(0.25,1.5) 7(-0.25,1.5) 8(-0.75,1.5)
XTAL_2SM_3R2X1R5
  rect 1.295x1.6 smd: 1(-1.15,0) 2(1.15,0)
XTAL_2SM_12R7X4R7
  rect 5.486x1.499 smd: 1(-4.25,0) 2(4.25,0)
XTAL_SOCKET
  round 2.108 hole 1.346: 1(0,0) 2(-5.08,0)

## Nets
+3V3: C43.2 C52.2 C60.2 C64.2 C65.1 C69.2 C70.2 C71.2 C72.2 C80.1 C81.1 CN13.4 CN16.9 CN16.10 JP12.1 LD1.1 LD2.1 LD3.1 LD4.1 R19.1 R44.1 R90.1 R92.1 R110.2 R128.2 R143.1 R145.2 R170.1 R198.1 SB41.1 TP20.1 U7.22 U7.26 U8.22 U8.26 U12.8 U13.8 U14.7 U17.8 U18.8 U19.8 U20.4
+3V3_PG: R148.2 R150.1 U20.3
+3V3_STLINK: C73.1 C97.2 C103.2 C107.2 C108.1 C115.1 CN15.4 JP13.1 R184.2 R208.2 T14.3 U16.5 U24.1 U24.9 U24.24 U24.36 U24.48 U26.8
+5V: C79.1 C82.1 C117.2 D7.1 JP11.1 JP11.3 JP11.5 JP11.7 LD7.1 R148.1 R151.1 R153.2 R156.1 SB40.1 TP22.1 U20.6 U22.6 U28.8
AGND: C1.1 C8.1 C9.2 C17.1 C18.2 C19.2 L1.2 R16.2 R21.2 R23.2 SB1.2 SB2.2 SB3.2 SB19.2 SB20.2 SB21.2 U1.1 U3.4 U4.4
D5V: CN4.24 D5.1 JP11.2
GND: B1.1 B1.4 C2.1 C3.1 C4.1 C5.1 C10.1 C11.1 C12.1 C13.1 C14.1 C15.1 C20.2 C21.1 C22.1 C23.1 C24.2 C25.2 C26.1 C27.2 C28.1 C29.1 C30.2 C31.2 C32.2 C33.1 C34.2 C35.1 C36.2 C37.1 C39.2 C41.2 C42.2 C43.1 C44.2 C46.1 C47.2 C48.2 C49.2 C51.2 C52.1 C54.1 C55.2 C56.1 C57.2 C58.2 C59.2 C60.1 C61.1 C62.1 C63.2 C64.1 C65.2 C66.1 C67.1 C68.2 C69.1 C70.1 C71.1 C72.1 C73.2 C74.2 C75.2 C76.1 C77.1 C78.1 C79.2 C80.2 C81.2 C82.2 C83.2 C84.1 C86.1 C87.2 C88.2 C89.1 C90.2 C91.1 C92.2 C93.1 C94.1 C95.1 C96.2 C97.1 C98.2 C99.1 C100.2 C101.1 C103.1 C104.2 C106.1 C107.1 C108.2 C109.2 C112.1 C113.1 C114.1 C115.2 C116.2 C117.1 C118.1 CN1.7 CN2.1 CN3.1 CN4.1 CN4.11 CN4.12 CN4.25 CN4.26 CN5.1 CN5.2 CN5.14 CN5.15 CN5.25 CN6.5 CN6.10 CN6.11 CN7.5 CN7.10 CN7.11 CN9.5 CN9.6 CN9.7 CN9.8 CN9.9 CN9.10 CN9.11 CN11.3 CN11.5 CN11.9 CN11.11 CN11.13 CN11.15 CN11.17 CN11.19 CN12.4 CN12.6 CN12.8 CN12.10 CN12.12 CN12.14 CN12.16 CN12.18 CN12.20 CN13.6 CN13.9 CN15.2 CN16.11 CN16.12 CN17.4 CN17.5 CN17.6 CN19.2 L1.1 L8.4 L8.5 L8.6 L10.1 LD5.2 LD6.1 R5.2 R46.1 R57.2 R64.2 R66.2 R74.1 R76.2 R91.2 R99.1 R102.1 R103.1 R104.1 R105.2 R106.1 R107.1 R109.1 R112.1 R113.1 R115.1 R123.2 R124.2 R125.2 R126.2 R127.2 R129.2 R147.2 R157.2 R167.2 R169.1 R172.2 R173.1 R174.2 R175.2 R182.1 R183.1 R185.2 R196.2 R203.1 R206.2 R212.2 R215.2 RV1.2 RV1.3 SB1.1 SB2.1 SB3.1 SB19.1 SB20.1 SB21.1 SW1.3 TP1.1 TP10.1 TP21.1 TP23.1 U2.4 U2.5 U2.6 U5.19 U5.20 U5.27 U5.49 U5.74 U5.99 U6.2 U6.7 U7.4 U7.12 U7.23 U7.25 U8.4 U8.12 U8.23 U8.25 U9.2 U10.2 U11.2 U12.4 U13.4 U14.8 U15.2 U16.2 U17.3 U17.4 U18.3 U18.4 U18.6 U19.4 U20.2 U20.7 U21.4 U22.2 U22.7 U23.4 U24.8 U24.23 U24.35 U24.47 U25.8 U25.23 U25.35 U25.47 U26.4 U28.4 U29.4
VDD: B2.1 B2.4 C3.2 C56.2 C67.2 C76.2 C77.2 C78.2 C83.1 C86.2 C91.2 C94.2 C99.2 C104.1 C106.2 C109.1 C116.1 CN1.5 CN5.26 CN11.1 CN12.1 CN12.2 JP10.1 L6.2 L7.1 R3.2 R6.1 R43.1 R53.2 R56.2 R83.2 R89.2 R94.2 R95.2 R100.2 R108.2 R117.2 R122.2 R136.2 R139.2 R155.1 R178.1 R186.1 R192.2 R213.2 SB4.2 SW1.1 T7.1 T7.2 T7.3 T8.4 T9.1 T9.2 T9.3 T10.4 T11.3 TP25.1 U2.8 U12.1 U12.5 U13.1 U13.5 U17.1 U17.5 U18.1 U19.1 U19.5 U23.8 U25.1 U25.24 U25.36 U25.48 U26.1 U26.5 U28.3 U28.5
VDD_ADJ: C92.1 C98.1 JP12.3 R154.1 TP24.1 U22.4
VDD_ANA: C1.2 C8.2 C9.1 C17.2 C18.1 R15.1 R22.2 R43.2 R44.2 U1.3 U3.8 U4.8
VDD_MCU: C13.2 C14.2 C28.2 C29.2 C37.2 JP4.1 JP5.1 JP7.1 JP10.2 R47.1 R180.2 U5.28 U5.50 U5.73 U5.100
VDD_PG: R60.1 R156.2 U22.3
VDD_USB: C31.1 C33.2 JP7.2 TP7.1 U5.75
VDDA: C20.1 C21.2 JP4.2 TP5.1 U5.22
AIN_1: R185.1 R186.2 U24.10
BOOT0: CN5.21 JP3.1 R36.1 U5.94
CAL: R125.1 T7.4 T8.3 U25.3
CAL_D: R133.2 T1.1 T1.2 T1.3 T2.4 T3.1 T3.2 T3.3 T4.4 T5.1 T5.2 T5.3 T6.4 T7.5 T7.6 T7.7 T7.8 T8.1 T8.2 T8.5 T8.6 U21.3
E5V: C96.1 D3.1 JP11.8 L8.3
IDD_MEAS: C101.2 R164.1 U25.25
IRDA_RX: JP9.1 U14.4
LC_H: C40.2 L2.4 L3.2 SB29.1
LC_L: C40.1 L2.1 L3.1 SB30.1
LCDCOM0: CN10.3 U5.67
LCDCOM1: CN10.1 U5.68
LCDCOM2: CN10.5 U5.69
LCDCOM3: CN10.7 U5.96
LCDCOM4: CN14.7 U5.78
LCDCOM5: CN14.5 U5.79
LCDCOM6: CN14.3 U5.80
LCDCOM7: CN14.1 U5.83
LCDSEG0: CN14.47 SB12.1
LCDSEG1: CN10.35 SB9.1
LCDSEG2: CN10.33 U5.26
LCDSEG3: CN10.41 U5.31
LCDSEG4: CN10.39 JP1.1 JP14.2 SB28.2
LCDSEG5: CN10.37 JP14.1 JP16.1 SB14.2 SB28.1 SB34.1
LCDSEG6: CN10.47 SB13.2
LCDSEG7: CN10.45 SB35.2
LCDSEG8: CN10.43 JP15.1 JP16.2 SB34.2
LCDSEG9: CN10.13 U5.91
LCDSEG10: CN10.11 U5.47
LCDSEG11: CN10.9 U5.48
LCDSEG12: CN10.19 SB5.2
LCDSEG13: CN10.17 SB16.2
LCDSEG14: CN10.15 U5.53
LCDSEG15: CN10.25 U5.54
LCDSEG16: CN10.23 U5.95
LCDSEG17: CN10.21 U5.77
LCDSEG18: CN10.31 JP17.1 JP18.2 SB36.2
LCDSEG19: CN10.29 JP18.1 SB36.1 U5.16
LCDSEG20: CN10.27 U5.17
LCDSEG21: CN14.9 U5.18
LCDSEG22: CN14.11 U5.33
LCDSEG23: CN14.13 U5.34
LCDSEG24: CN14.15 SB18.1
LCDSEG25: CN14.17 SB22.1
LCDSEG26: CN14.19 U5.65
LCDSEG27: CN14.21 U5.66
LCDSEG28: CN14.23 U5.55
LCDSEG29: CN14.25 U5.56
LCDSEG30: CN14.27 U5.57
LCDSEG31: CN14.29 U5.58
LCDSEG32: CN14.31 U5.59
LCDSEG33: CN14.33 U5.60
LCDSEG34: CN14.35 U5.61
LCDSEG35: CN14.37 U5.62
LCDSEG36: CN14.39 U5.97
LCDSEG37: CN14.41 U5.98
LCDSEG38: CN14.43 U5.1
LCDSEG39: CN14.45 U5.2
LED_STLINK: R204.1 R209.1 U24.30
LPUART_RTS_3V3: U8.14 U12.6
MCO: U24.29
MFX_SWCLK: CN19.3 U25.37
MFX_SWDIO: CN19.1 U25.34
MICROB_N: CN9.2 R69.2 U10.3 U10.4
MICROB_P: CN9.3 R70.2 U10.1 U10.6
NETB2_2: B2.2 B2.3 R214.1 R215.1
NETB3_1: B3.1 U25.20
NETB3_2: B3.2 U25.18
NETB3_3: B3.3 U25.19
NETB3_4: B3.4 U25.39
NETB3_5: B3.5 R203.2
NETB3_6: B3.6 U25.40
NETC2_2: C2.2 R7.2 R8.1
NETC4_2: C4.2 SB7.2
NETC5_2: C5.2 SB10.1
NETC6_1: C6.1 R11.1 R14.2 R15.2 U3.2
NETC6_2: C6.2 R14.1 R20.2 U3.1
NETC7_1: C7.1 R11.2 R16.1 R17.2 U3.6
NETC7_2: C7.2 R17.1 R33.2 U3.7
NETC10_2: C10.2 R25.2 TP3.1
NETC11_2: C11.2 R26.2 TP4.1
NETC12_2: C12.2 R27.2 TP2.1
NETC15_2: C15.2 R28.2 R29.1
NETC16_1: C16.1 R31.1 U4.7
NETC16_2: C16.2 R30.1 R31.2 U4.6
NETC19_1: C19.1 R34.1 R38.1
NETC22_2: C22.2 SB15.2
NETC25_1: C25.1 R42.2 X1.1
NETC26_2: C26.2 SB24.1
NETC30_1: C30.1 R48.1 X2.1
NETC34_1: C34.1 R49.1 X2.2
NETC35_2: C35.2 R50.2 TP8.1
NETC38_1: C38.1 U7.1
NETC38_2: C38.2 U7.2
NETC39_1: C39.1 U7.27
NETC41_1: C41.1 R60.2 U6.1
NETC42_1: C42.1 U7.3
NETC45_1: C45.1 U7.24
NETC45_2: C45.2 U7.28
NETC46_2: C46.2 CN8.1 R67.1 SB30.2 SB33.1 TP14.1
NETC47_1: C47.1 R54.2 R64.1 U11.3
NETC50_1: C50.1 U8.24
NETC50_2: C50.2 U8.28
NETC51_1: C51.1 U8.3
NETC53_1: C53.1 U8.1
NETC53_2: C53.2 U8.2
NETC55_1: C55.1 U8.27
NETC57_1: C57.1 R73.2 R76.1 U9.1
NETC58_1: C58.1 R54.1 SB32.1 U11.5
NETC59_1: C59.1 JP2.3
NETC61_2: C61.2 CN13.5 L4.2 R75.1
NETC62_2: C62.2 CN13.3 L11.2 R135.2
NETC63_1: C63.1 R73.1 SB31.1 U9.5
NETC66_2: C66.2 C68.1 R92.2 U14.6
NETC74_1: C74.1 D3.2 D4.2 D5.2 D6.2 U16.1 U16.3
NETC75_1: C75.1 U16.4
NETC84_2: C84.2 L12.2 R72.1 R128.1
NETC87_1: C87.1 C88.1 R151.2 U21.8
NETC89_2: C89.2 R150.2 U22.1
NETC90_1: C90.1 C93.2 L7.2 U25.9
NETC95_2: C95.2 D8.1 R155.2 U25.7
NETC100_1: C100.1 R167.1 R170.2 U23.3
NETC102_1: C102.1 R162.2 R165.1 U23.6
NETC102_2: C102.2 R164.2 R165.2 U23.7
NETC105_1: C105.1 L8.1 U27.3 Z1.2
NETC105_2: C105.2 CN18.2 CN18.3 L8.2 U27.2 Z1.1
NETC110_1: C110.1 C111.1 CN16.13 CN16.14 L9.2
NETC110_2: C110.2 C111.2 CN16.15 CN16.16 L10.2
NETCN1_1: CN1.1 R1.2
NETCN1_3: CN1.3 R2.2
NETCN1_4: CN1.4 CN14.44 R3.1
NETCN2_2: CN2.2 R7.1
NETCN3_2: CN3.2 R28.1
NETCN4_2: CN4.2 R19.2
NETCN5_7: CN5.7 SB23.2
NETCN5_8: CN5.8 SB25.2
NETCN5_11: CN5.11 SB27.2
NETCN5_12: CN5.12 SB26.2
NETCN5_13: CN5.13 R39.2
NETCN5_24: CN5.24 R41.2
NETCN6_2: CN6.2 U7.6
NETCN6_3: CN6.3 U7.10
NETCN6_6: CN6.6 U7.5
NETCN6_7: CN6.7 U7.9
NETCN6_8: CN6.8 U7.7
NETCN7_2: CN7.2 U8.6
NETCN7_3: CN7.3 U8.10
NETCN7_6: CN7.6 U8.5
NETCN7_7: CN7.7 U8.9
NETCN7_8: CN7.8 U8.7
NETCN8_2: CN8.2 R59.1 SB29.2
NETCN9_4: CN9.4 R74.2
NETCN10_14: CN10.14 R4.2
NETCN11_2: CN11.2 CN12.7 R98.1 R100.1 U15.4
NETCN11_4: CN11.4 CN12.9 R97.1 R99.2 U15.5
NETCN11_10: CN11.10 CN12.15 R111.1 U15.1
NETCN12_11: CN12.11 R108.1 R109.2
NETCN12_17: CN12.17 R113.2
NETCN12_19: CN12.19 R115.2
NETCN13_2: CN13.2 R110.1 R119.1 R120.2
NETCN13_7: CN13.7 R112.2 R114.1 R144.1
NETCN13_10: CN13.10 R116.2
NETCN14_12: CN14.12 R101.2
NETCN14_20: CN14.20 R102.2
NETCN14_22: CN14.22 R103.2
NETCN14_24: CN14.24 R87.1
NETCN14_26: CN14.26 R62.1
NETCN14_30: CN14.30 R61.1
NETCN14_32: CN14.32 R88.1
NETCN14_34: CN14.34 R104.2
NETCN14_36: CN14.36 R105.1
NETCN14_38: CN14.38 R106.2
NETCN14_40: CN14.40 R107.2
NETCN16_1: CN16.1 R72.2
NETCN16_2: CN16.2 R75.2
NETCN16_3: CN16.3 R135.1
NETCN16_7: CN16.7 R144.2
NETCN16_8: CN16.8 R145.1 T11.1 T11.2 T11.5 T11.6
NETCN17_2: CN17.2 R193.2
NETCN17_3: CN17.3 R194.2 R195.2
NETCN18_1: CN18.1 U27.1
NETCN19_4: CN19.4 R192.1
NETD1_1: D1.1 R35.1
NETD1_2: D1.2 JP3.2
NETD2_1: D2.1 JP6.2
NETD2_2: D2.2 R63.1 U7.16
NETD7_2: D7.2 R168.2
NETJP1_3: JP1.3 JP17.3 TP18.1
NETJP2_1: JP2.1 R29.2
NETJP5_2: JP5.2 R40.1 TP6.1
NETJP8_1: JP8.1 R59.2
NETJP8_2: JP8.2 JP15.3
NETJP9_3: JP9.3 U7.17
NETJP10_3: JP10.3 R130.1 R131.1 R132.1 R133.1 R134.1 U21.5
NETJP11_4: JP11.4 L5.1 SB38.2
NETJP12_2: JP12.2 L6.1
NETL9_1: L9.1 SB40.2 SB41.2
NETL12_1: L12.1 R141.2 R142.1
NETLD1_2: LD1.2 R202.2
NETLD2_2: LD2.2 R201.2
NETLD3_2: LD3.2 R200.2
NETLD4_2: LD4.2 R199.2
NETLD5_1: LD5.1 R153.1
NETLD6_2: LD6.2 R204.2
NETLD6_3: LD6.3 R209.2
NETLD6_4: LD6.4 R208.1
NETLD7_2: LD7.2 R210.1
NETLD8_1: LD8.1 R210.2 U28.1
NETLD8_2: LD8.2 R211.1
NETLD9_1: LD9.1 R211.2 U28.7
NETLD9_2: LD9.2 R212.1
NETLD10_1: LD10.1 R65.2
NETLD10_2: LD10.2 R68.2 U29.8
NETLS1_1: LS1.1 LS1.4 R18.2
NETLS1_2: LS1.2 R12.2
NETLS1_3: LS1.3 R13.2
NETR1_1: R1.1 R10.1 R52.2 R53.1 R177.1
NETR2_1: R2.1 R9.1 R55.2 R56.1 R179.1
NETR4_1: R4.1 R6.2 U2.3
NETR5_1: R5.1 SB4.1 U2.7
NETR9_2: R9.2 U2.2
NETR10_2: R10.2 U2.1
NETR12_1: R12.1 SB8.2
NETR13_1: R13.1 SB11.1
NETR18_1: R18.1 SB6.2
NETR20_1: R20.1 R21.1 R22.1 U4.3
NETR23_1: R23.1 R24.2
NETR24_1: R24.1 U4.5
NETR32_1: R32.1 R34.2 U4.1
NETR32_2: R32.2 R33.1 U4.2
NETR35_2: R35.2 U7.20
NETR36_2: R36.2 SW1.2
NETR37_2: R37.2 SB17.1
NETR57_1: R57.1 R58.2 U6.5
NETR61_2: R61.2 U8.16
NETR62_2: R62.2 U8.17
NETR66_1: R66.1 U29.5
NETR67_2: R67.2 U9.3 U9.4
NETR83_1: R83.1 R87.2 U12.2
NETR88_2: R88.2 R89.1 U12.3
NETR90_2: R90.2 U14.1
NETR91_1: R91.1 U14.5
NETR93_1: R93.1 R94.1 U13.2
NETR95_1: R95.1 R96.1 U13.3
NETR101_1: R101.1 R117.1 R118.1 U18.5
NETR116_1: R116.1 U25.15
NETR119_2: R119.2 U19.7
NETR121_1: R121.1 R122.1 U19.2
NETR129_1: R129.1 R143.2 U20.5
NETR136_1: R136.1 R137.1 U17.2
NETR138_1: R138.1 U18.2
NETR139_1: R139.1 R140.2 U19.3
NETR142_2: R142.2 U19.6
NETR147_1: R147.1 U20.1
NETR149_1: R149.1 R154.2 U22.5
NETR149_2: R149.2 RV1.1
NETR157_1: R157.1 R158.2 U25.2
NETR159_1: R159.1 U21.1 U21.2
NETR159_2: R159.2 R163.1 U23.5
NETR162_1: R162.1 U21.6 U21.7
NETR163_2: R163.2 U23.1 U23.2
NETR166_2: R166.2 U25.46
NETR169_2: R169.2 U25.45
NETR171_1: R171.1 U25.17
NETR171_2: R171.2 U25.16
NETR172_1: R172.1 U24.20
NETR174_1: R174.1 U25.44
NETR175_1: R175.1 U24.44
NETR176_1: R176.1 U25.21
NETR176_2: R176.2 U25.22
NETR177_2: R177.2 U25.43
NETR178_2: R178.2 R181.2 U26.2
NETR179_2: R179.2 U25.42
NETR180_1: R180.1 U25.41
NETR182_2: R182.2 U24.2
NETR183_2: R183.2 U24.3
NETR187_1: R187.1 U24.12
NETR188_1: R188.1 U25.28
NETR188_2: R188.2 U25.27
NETR189_1: R189.1 U25.30
NETR189_2: R189.2 U25.29
NETR190_1: R190.1 U25.32
NETR190_2: R190.2 U25.31
NETR191_1: R191.1 U25.26
NETR191_2: R191.2 U25.33
NETR195_1: R195.1 T14.2
NETR196_1: R196.1 R197.2 U28.2
NETR197_1: R197.1 R198.2 U28.6
NETR205_2: R205.2 R206.1 R207.2 T14.1
NETSB33_2: SB33.2 U11.1 U11.4
NETTP26_1: TP26.1 U25.11
NETTP27_1: TP27.1 U25.10
NETTP28_1: TP28.1 U24.21
NETTP29_1: TP29.1 U25.12
NETTP31_1: TP31.1 U25.14
NETU1_2: U1.2 U3.3
NETU1_4: U1.4 U3.5
NETU7_13: U7.13 U13.7 U14.3
NETU8_13: U8.13 U12.7
NETU24_13: U24.13 U26.7
OSC_IN: C112.2 U24.5 X3.2
OSC_OUT: C113.2 U24.6 X3.1
PA0: CN5.5 R38.2 U5.23
PA1: SB11.2 SB12.2 U5.24
PA2: SB9.2 SB10.2 U5.25
PA4: CN5.6 JP2.2 U5.29
PA5: CN5.3 R8.2 U5.30
PA7: JP1.2 U5.32
PA11: CN4.14 R69.1 U5.70
PA12: CN4.16 R70.1 U5.71
PA13: CN4.15 R45.2 U5.72
PA14: CN4.18 R51.2 U5.76
PB0: SB8.1 SB14.1 U5.35
PB1: SB7.1 SB13.1 U5.36
PB2: CN5.4 R27.1 U5.37
PB3: SB35.1 U5.89
PB4: JP15.2 U5.90
PB6: CN5.23 R55.1 U5.92
PB7: CN5.22 R52.1 U5.93
PB12: SB5.1 SB6.1 U5.51
PB13: SB15.1 SB16.1 U5.52
PC0: JP17.2 U5.15
PC6: SB17.2 SB18.2 U5.63
PC7: SB22.2 SB24.2 U5.64
PC13: R39.1 R214.2 U5.7
PC14: R49.2 SB27.1 U5.8
PC15: R48.2 SB26.1 U5.9
PD0: CN4.17 R120.1 R121.2 U5.81
PD1: CN4.20 R200.1 U5.82
PD3: CN4.19 R63.2 U5.84
PD4: R96.2 U5.85
PD5: CN4.22 R93.2 U5.86
PD6: CN4.21 JP9.2 U5.87
PD7: CN4.23 SB31.2 SB32.2 U5.88
PE4: CN5.20 R202.1 U5.3
PE5: CN5.19 R201.1 U5.4
PE6: CN5.18 R166.1 U5.5
PE7: CN4.3 R199.1 U5.38
PE8: CN4.4 R181.1 U5.39
PE9: CN4.5 R187.2 U5.40
PE10: CN4.6 R140.1 R141.1 U5.41
PE11: CN4.7 R26.1 U5.42
PE12: CN4.8 R25.1 U5.43
PE13: CN4.9 R137.2 U5.44
PE14: CN4.10 R114.2 U5.45
PE15: CN4.13 R138.2 U5.46
PH0: C27.1 SB25.1 U5.12 X1.2
PH1: R42.1 SB23.1 U5.13
PH9: CN5.10 R46.2 R118.2 U5.10
PH10: CN5.9 R47.2 R158.1 U5.11
PWR_ENN: R71.1 U24.28 U29.3
PWR_EXT: JP13.2 R168.1 R173.2 U24.39
RESET#: B1.2 B1.3 C118.2 D8.2 JP6.1 R41.1 R111.2 R213.1 T11.4 U5.14 U24.18
SH0: R126.1 T9.4 T10.3 U25.4
SH0_D: R134.2 T9.5 T9.6 T9.7 T9.8 T10.1 T10.2 T10.5 T10.6
SH1: R123.1 T3.4 T4.3 U25.5
SH1_D: R131.2 T3.5 T3.6 T3.7 T3.8 T4.1 T4.2 T4.5 T4.6
SH2: R127.1 T1.4 T2.3 U25.6
SH2_D: R130.2 T1.5 T1.6 T1.7 T1.8 T2.1 T2.2 T2.5 T2.6
SH3: R124.1 T5.4 T6.3 U25.38
SH3_D: R132.2 T5.5 T5.6 T5.7 T5.8 T6.1 T6.2 T6.5 T6.6
SPI1_MOSI_3V3: L11.1 U18.7
SPI1_SCK_3V3: L4.1 U17.7
STL_USB_DM: R193.1 U24.32
STL_USB_DP: R194.1 U24.33
STM_JTCK_SWCLK: CN15.3 U24.37
STM_JTMS_SWDIO: CN15.1 U24.34
STM_RST: C114.2 R184.1 U24.7
SWIM_PU_CTRL: U24.4
T_JRST: U24.19
T_JTCK: R51.1 R97.2 U24.15 U24.26
T_JTDI: U24.17
T_JTDO: U24.16
T_JTMS: R45.1 R98.2 U24.27 U26.3
T_SWDIO_IN: U24.25 U26.6
T_SWO: U24.31
TS_SHIELD: R37.1
U5V: C44.1 C49.1 CN9.1 D4.1 JP11.6 U6.6 U10.5
U5V_STLINK: C54.2 L5.2 SB38.1 U29.6 U29.7
USART2_RTS_3V3: U7.14 U13.6
USB_RENUMN: R205.1 U24.38
USB_VBUS3V3: C32.1 C36.1 JP7.3 R58.1 TP9.1 U6.4
VLCD: CN5.17 R50.1 U5.6
VREF+: C23.2 C24.1 R40.2 U5.21
VUSB_STLINK: C48.1 CN17.1 D6.1 R65.1 R68.1 R71.2 R207.1 U29.1 U29.2

Pads without a net: B3 7 8; CN1 2 6 8; CN5 16; CN6 1 4 9; CN7 1 4 9; CN10 2 4 6 8 10 12 16 18 20 22 24 26 28 30 32 34 36 38 40 42 44 46 48; CN11 6 7 8 12 14 16 18 20; CN12 3 5 13; CN13 1 8 11 12 13 14; CN14 2 4 6 8 10 14 16 18 28 42 46 48; CN15 5; CN16 4 5 6; CN19 5; L2 2 3 5 6 7 8; R30 2; U1 5; U5 0/3 0/4 0/5 0/6; U6 3; U7 8 11 15 18 19 21; U8 8 11 15 18 19 20 21; U14 2; U15 3; U17 6; U24 11 14 22 40 41 42 43 45 46; U25 13

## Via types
v1: diameter 0.61, hole 0.305, TOP to BOTTOM, 669 vias

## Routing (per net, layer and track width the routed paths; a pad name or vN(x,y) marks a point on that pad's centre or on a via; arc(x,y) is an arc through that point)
+3V3: length 98
  TOP w0.254: U18.8 34.68,59.04 34.04,59.69 34.04,60.2 C71.2 ; U17.8 30.24,58.41 29.59,59.05 C70.2
  TOP w0.279: U19.8 38.24,60.06 C72.2 ; C60.2 96.25,96.14 U12.8 ; 16.64,88.52 16.66,88.5 U13.8
  TOP w0.305: U7.26 26.67,111.13 C43.2 ; U7.22 v1(23.42,108.53) ; C52.2 88.78,101.6 U8.26
  TOP w0.356: v1(90.42,104.39) 90.23,104.2 U8.22
  TOP w0.508: R44.1 98.17,109.09 v1(99.01,108.25) ; v1(26.67,110.24) 26.8,110.36 C43.2 ; v1(15.6,88.21) 15.9,88.52 16.64,88.52 ; LD4.1 v1(55.63,11.18) ; 26.62,50.42 C80.1 ; C80.1 27.43,51.17 ; C80.1 28.25,50.42 ; R143.1 25.27,53.29 ; R143.1 25.27,52.12 ; R143.1 25.85,52.7 ; R170.1 v1(92.33,32) ; v1(19.81,71.5) 19.81,71.25 R110.2 ; LD1.1 v1(63.25,11.18) ; C71.2 33.4,59.82 v1(33.4,59.31) ; 10.29,87.76 v1(10.29,86.36) ; U14.7 5.3,83.99 5.97,83.31 C69.2 v1(6.73,82.04) ; C52.2 v1(86.74,102.36) ; LD2.1 v1(60.71,11.18) ; SB41.1 v1(92.08,27.18) ; v1(37.59,59.56) 37.59,59.94 C72.2 ; R128.2 v1(92.33,55.24) ; R90.1 v1(8.51,89.66) ; C60.2 v1(97.79,97.03) ; R92.1 v1(8.64,84.58) ; 25.87,50.58 U20.4 25.46,51.12 ; 28.63,50.04 C81.1 ; C81.1 29.54,50.04 ; C81.1 29.08,50.5 ; R19.1 v1(27.81,144.15) ; v1(20.32,11.68) 24,15.37 27.18,15.37 28.32,16.51 R198.1 ; v1(28.83,60.33) C70.2 ; LD3.1 v1(58.17,11.18) ; CN13.4 v1(13.83,69.08) ; R145.2 v1(89.28,46.35)
  BOTTOM w0.508: v1(55.63,11.18) v1(58.17,11.18) v1(60.71,11.18) v1(63.25,11.18) v1(63.25,4.83)
  vias: v1(27.56,51.69) v1(28.32,51.44) v1(28.96,50.93)
